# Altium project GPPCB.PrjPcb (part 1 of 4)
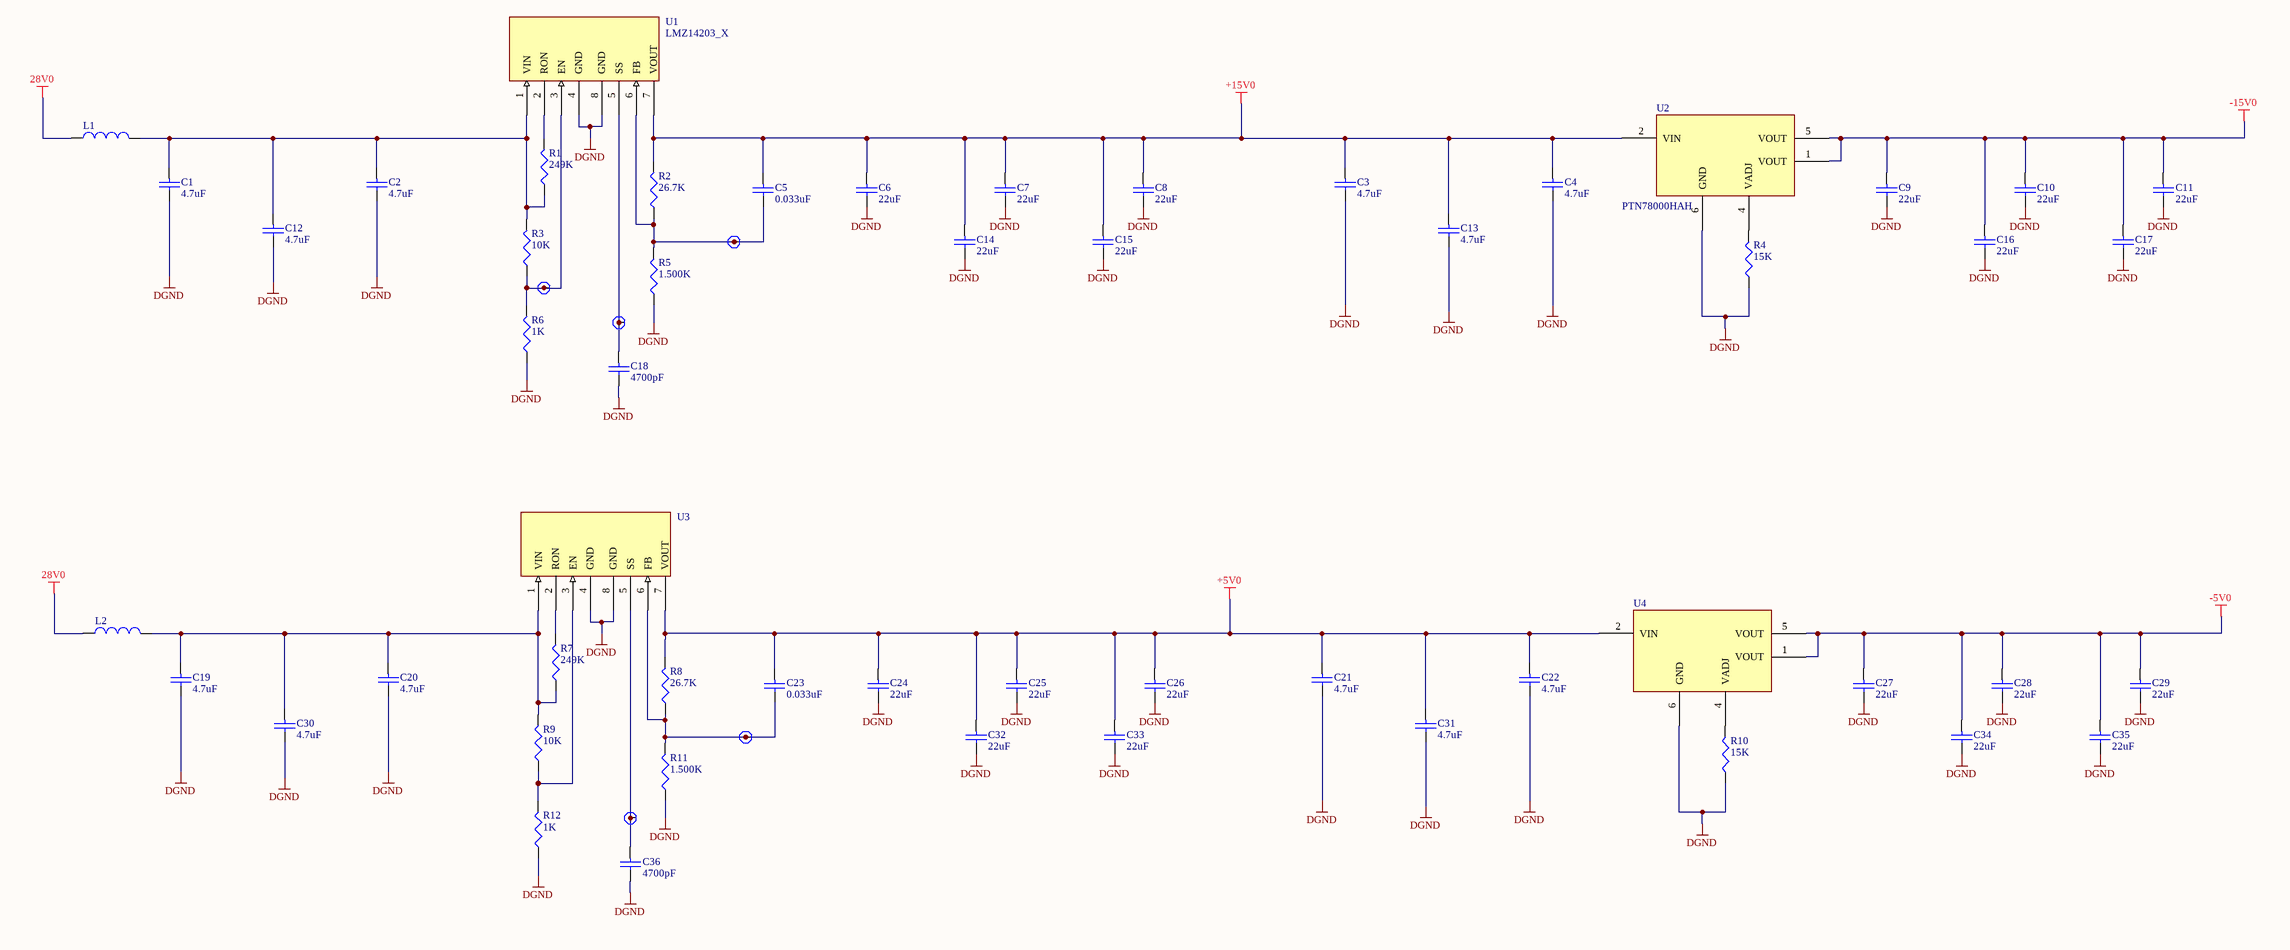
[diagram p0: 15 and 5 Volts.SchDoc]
15 sheets, 562 parts. Net scope: flat (ports and power ports of the same name join across sheets).
Board file: PCB2.PcbDoc
Sheets:
  15 and 5 Volts.SchDoc
  28 PowerSupply.SchDoc
  ByPass.SchDoc
  Connector.SchDoc
  Controller.SchDoc
  Decoder.SchDoc
  Latch1.SchDoc
  Latch2.SchDoc
  Latch3.SchDoc
  Latch4.SchDoc
  Latch5.SchDoc
  Latch6.SchDoc
  Latch7.SchDoc
  Protection.SchDoc
  Protection1.SchDoc

## Sheet 15 and 5 Volts.SchDoc: P.C. BOARD
size A2; Revision: A; SheetNumber: 2; SheetTotal: 19

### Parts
C1  value 4.7uF  [1210/2.8/N]  (hidden comment: 475-50V-10CX1210)
C2  value 4.7uF  [1210/2.8/N]  (hidden comment: 475-50V-10CX1210)
C3  value 4.7uF  [1210/2.8/N]  (hidden comment: 475-50V-10CX1210)
C4  value 4.7uF  [1210/2.8/N]  (hidden comment: 475-50V-10CX1210)
C5  value 0.033uF  [0805/1.3/N]  (hidden comment: 333-50V-10CX0805)
C6  value 22uF  [1210/2.8/N]  (hidden comment: 226-25V-10CX1210)
C7  value 22uF  [1210/2.8/N]  (hidden comment: 226-25V-10CX1210)
C8  value 22uF  [1210/2.8/N]  (hidden comment: 226-25V-10CX1210)
C9  value 22uF  [1210/2.8/N]  (hidden comment: 226-25V-10CX1210)
C10  value 22uF  [1210/2.8/N]  (hidden comment: 226-25V-10CX1210)
C11  value 22uF  [1210/2.8/N]  (hidden comment: 226-25V-10CX1210)
C12  value 4.7uF  [1210/2.8/N]  (hidden comment: 475-50V-10CX1210)
C13  value 4.7uF  [1210/2.8/N]  (hidden comment: 475-50V-10CX1210)
C14  value 22uF  [1210/2.8/N]  (hidden comment: 226-25V-10CX1210)
C15  value 22uF  [1210/2.8/N]  (hidden comment: 226-25V-10CX1210)
C16  value 22uF  [1210/2.8/N]  (hidden comment: 226-25V-10CX1210)
C17  value 22uF  [1210/2.8/N]  (hidden comment: 226-25V-10CX1210)
C18  value 4700pF  [0805/1.3/N]  (hidden comment: 472-101-10CX0805)
C19  value 4.7uF  [1210/2.8/N]  (hidden comment: 475-50V-10CX1210)
C20  value 4.7uF  [1210/2.8/N]  (hidden comment: 475-50V-10CX1210)
C21  value 4.7uF  [1210/2.8/N]  (hidden comment: 475-50V-10CX1210)
C22  value 4.7uF  [1210/2.8/N]  (hidden comment: 475-50V-10CX1210)
C23  value 0.033uF  [0805/1.3/N]  (hidden comment: 333-50V-10CX0805)
C24  value 22uF  [1210/2.8/N]  (hidden comment: 226-25V-10CX1210)
C25  value 22uF  [1210/2.8/N]  (hidden comment: 226-25V-10CX1210)
C26  value 22uF  [1210/2.8/N]  (hidden comment: 226-25V-10CX1210)
C27  value 22uF  [1210/2.8/N]  (hidden comment: 226-25V-10CX1210)
C28  value 22uF  [1210/2.8/N]  (hidden comment: 226-25V-10CX1210)
C29  value 22uF  [1210/2.8/N]  (hidden comment: 226-25V-10CX1210)
C30  value 4.7uF  [1210/2.8/N]  (hidden comment: 475-50V-10CX1210)
C31  value 4.7uF  [1210/2.8/N]  (hidden comment: 475-50V-10CX1210)
C32  value 22uF  [1210/2.8/N]  (hidden comment: 226-25V-10CX1210)
C33  value 22uF  [1210/2.8/N]  (hidden comment: 226-25V-10CX1210)
C34  value 22uF  [1210/2.8/N]  (hidden comment: 226-25V-10CX1210)
C35  value 22uF  [1210/2.8/N]  (hidden comment: 226-25V-10CX1210)
C36  value 4700pF  [0805/1.3/N]  (hidden comment: 472-101-10CX0805)
L1  2773019447_X  [SM-118/157]  (value not drawn)
L2  2773019447_X  [SM-118/157]  (value not drawn)
R1  value 249K  [0805/N]  (hidden comment: R249K0D1#0AX0805)
R2  value 26.7K  [0603/N]  (hidden comment: R26K70D1#0GX0603)
R3  value 10K  [0805/N]  (hidden comment: R10K00D1#0AX0805)
R4  value 15K  [0805/N]  (hidden comment: R15K00D1#0AX0805)
R5  value 1.500K  [0603/N]  (hidden comment: R1K500Z5#0AX0603)
R6  value 1K  [0805/N]  (hidden comment: R1K000D1#0AX0805)
R7  value 249K  [0805/N]  (hidden comment: R249K0D1#0AX0805)
R8  value 26.7K  [0603/N]  (hidden comment: R26K70D1#0GX0603)
R9  value 10K  [0805/N]  (hidden comment: R10K00D1#0AX0805)
R10  value 15K  [0805/N]  (hidden comment: R15K00D1#0AX0805)
R11  value 1.500K  [0603/N]  (hidden comment: R1K500Z5#0AX0603)
R12  value 1K  [0805/N]  (hidden comment: R1K000D1#0AX0805)
TP1  TP_SMT  [TP_SMT]  (value not drawn)
TP2  TP_SMT  [TP_SMT]  (value not drawn)
TP3  TP_SMT  [TP_SMT]  (value not drawn)
TP4  TP_SMT  [TP_SMT]  (value not drawn)
TP5  TP_SMT  [TP_SMT]  (value not drawn)
U1  LMZ14203_X  [TO-PMOD-7]
U2  PTN78000HAH  [R_PDSS_T5]
U3  LMZ14203_X  [TO-PMOD-7]  (value not drawn)
U4  PTN78000HAH  [R_PDSS_T5]  (value not drawn)

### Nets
28V0: L1.1 L2.1
+5V0: C21.1 C22.1 C23.1 C24.1 C25.1 C26.1 C31.1 C32.1 C33.1 R8.2 U3.7(VOUT) U4.2(VIN)
+15V0: C3.1 C4.1 C5.1 C6.1 C7.1 C8.1 C13.1 C14.1 C15.1 R2.2 U1.7(VOUT) U2.2(VIN)
-5V0: C27.1 C28.1 C29.1 C34.1 C35.1 U4.1(VOUT) U4.5(VOUT)
-15V0: C9.1 C10.1 C11.1 C16.1 C17.1 U2.1(VOUT) U2.5(VOUT)
DGND: C1.2 C2.2 C3.2 C4.2 C6.2 C7.2 C8.2 C9.2 C10.2 C11.2 C12.2 C13.2 C14.2 C15.2 C16.2 C17.2 C18.2 C19.2 C20.2 C21.2 C22.2 C24.2 C25.2 C26.2 C27.2 C28.2 C29.2 C30.2 C31.2 C32.2 C33.2 C34.2 C35.2 C36.2 R4.1 R5.1 R6.1 R10.1 R11.1 R12.1 U1.4(GND) U1.8(GND) U2.6(GND) U3.4(GND) U3.8(GND) U4.6(GND)
NetC1_1: C1.1 C2.1 C12.1 L1.2 R1.1 R3.2 U1.1(VIN)
NetC5_2: C5.2 R2.1 R5.2 TP1.1(TP) U1.6(FB)
NetC18_1: C18.1 TP3.1(TP) U1.5(SS)
NetC19_1: C19.1 C20.1 C30.1 L2.2 R7.1 R9.2 U3.1(VIN)
NetC23_2: C23.2 R8.1 R11.2 TP4.1(TP) U3.6(FB)
NetC36_1: C36.1 TP5.1(TP) U3.5(SS)
NetR1_2: R1.2 U1.2(RON)
NetR3_1: R3.1 R6.2 TP2.1(TP) U1.3(EN)
NetR4_2: R4.2 U2.4(VADJ)
NetR7_2: R7.2 U3.2(RON)
NetR9_1: R9.1 R12.2 U3.3(EN)
NetR10_2: R10.2 U4.4(VADJ)

Not connected (* = marked no-connect by the designer): U2 3(INH); U4 3(INH)

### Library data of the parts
C1-C4 C12 C13 C19-C22 C30 C31 = 475-50V-10CX1210: CAPACITOR, CERAMIC, 4.7UF 10%, X7R, 50V, 1210; AREA: 0.0174; TOLERANCE: 10; TYPE: CAP_X
C5 C23 = 333-50V-10CX0805: CAPACITOR, CERAMIC, 0.033UF 10%, X7R, 50V, 0805; AREA: 0.0066; TOLERANCE: 10; TYPE: CAP_X
C6-C11 C14-C17 C24-C29 C32-C35 = 226-25V-10CX1210: CAPACITOR, CERAMIC, 22UF 10%, X7R, 25V, 1210; AREA: 0.0174; TOLERANCE: 10; TYPE: CAP_X
C18 C36 = 472-101-10CX0805: CAPACITOR, CERAMIC, 4700PF 10%, X7R, 100V; AREA: 0.0066; TOLERANCE: 10; TYPE: CAP_X
L1 L2 = 2773019447_X: INDUCTOR, BEAD, SMT, < 50 MHz (73 material); AREA: 0.022; TYPE: CHOKE
R1 R7 = R249K0D1#0AX0805: RESISTOR, 249K OHMS, 1%, 0805; AMETEK PART NO: B1604-097; AREA: 0.0085; TOLERANCE: 1; DESIGNER: GRL 12/09/03
R2 R8 = R26K70D1#0GX0603: RESISTOR, 26.7K OHM, 1%, 100 PPM, 0603; AREA: 0.0055; TOLERANCE: 1
R3 R9 = R10K00D1#0AX0805: RESISTOR, 10K OHM, 1%, 100 PPM, 0805; AREA: 0.0085; TOLERANCE: 1
R4 R10 = R15K00D1#0AX0805: RESISTOR, 15K, 1%, 100 PPM, 0805; AREA: 0.0066; TOLERANCE: 1
R5 R11 = R1K500Z5#0AX0603: RESISTOR, 1.500K OHM, 5%, 200 PPM, 0603; AREA: 0.0055; TOLERANCE: 5
R6 R12 = R1K000D1#0AX0805: RESISTOR, 1K, 1%, 100 PPM, 0805; AREA: 0.0085; TOLERANCE: 1
TP1-TP5 = TP35: TEST POINT, 0.035 dia Oct pad w/ 0.010 hole, or SMT; AREA: 0.0012
U1 U3 = LMZ14203_X: 3A POWER MODULE, 42V MAX; AREA: 0.228
U2 U4 = PTN78000HAH: MODULE, 11.85V - 22V SWITCHING REGULATOR (1.5A); AREA: 0.42

## Sheet 28 PowerSupply.SchDoc: P.C. BOARD
size A2; Revision: A; SheetNumber: 1; SheetTotal: 19
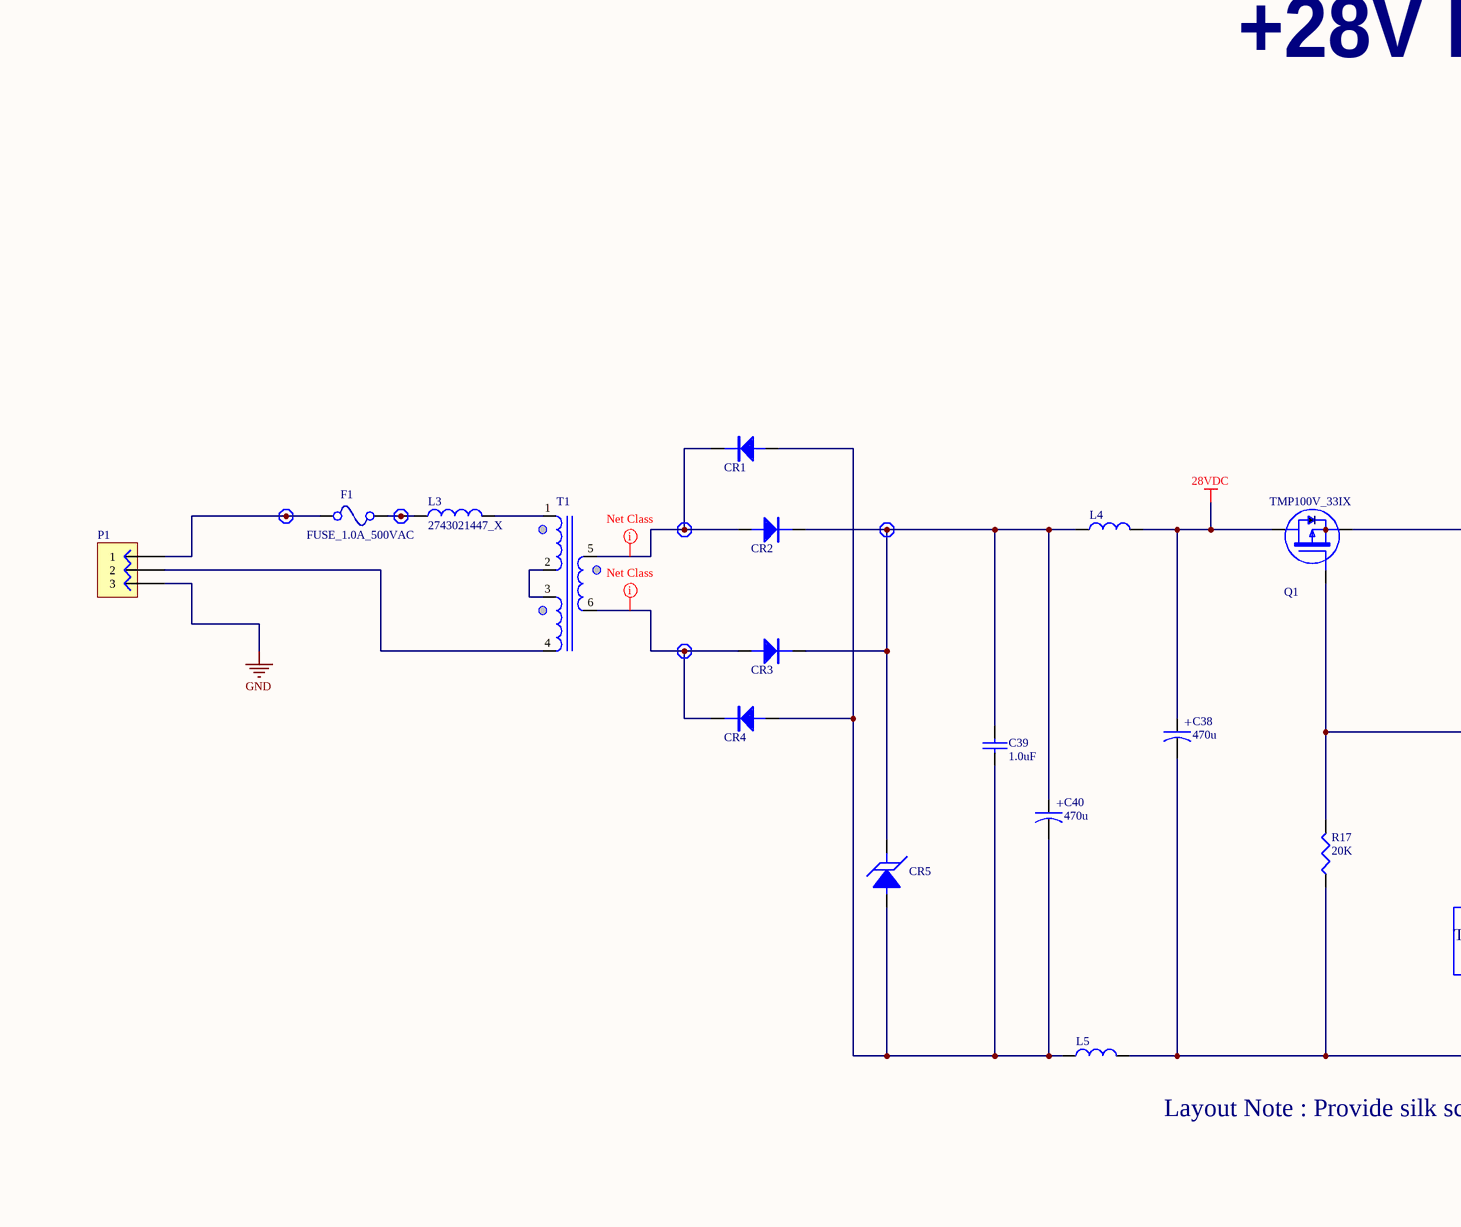
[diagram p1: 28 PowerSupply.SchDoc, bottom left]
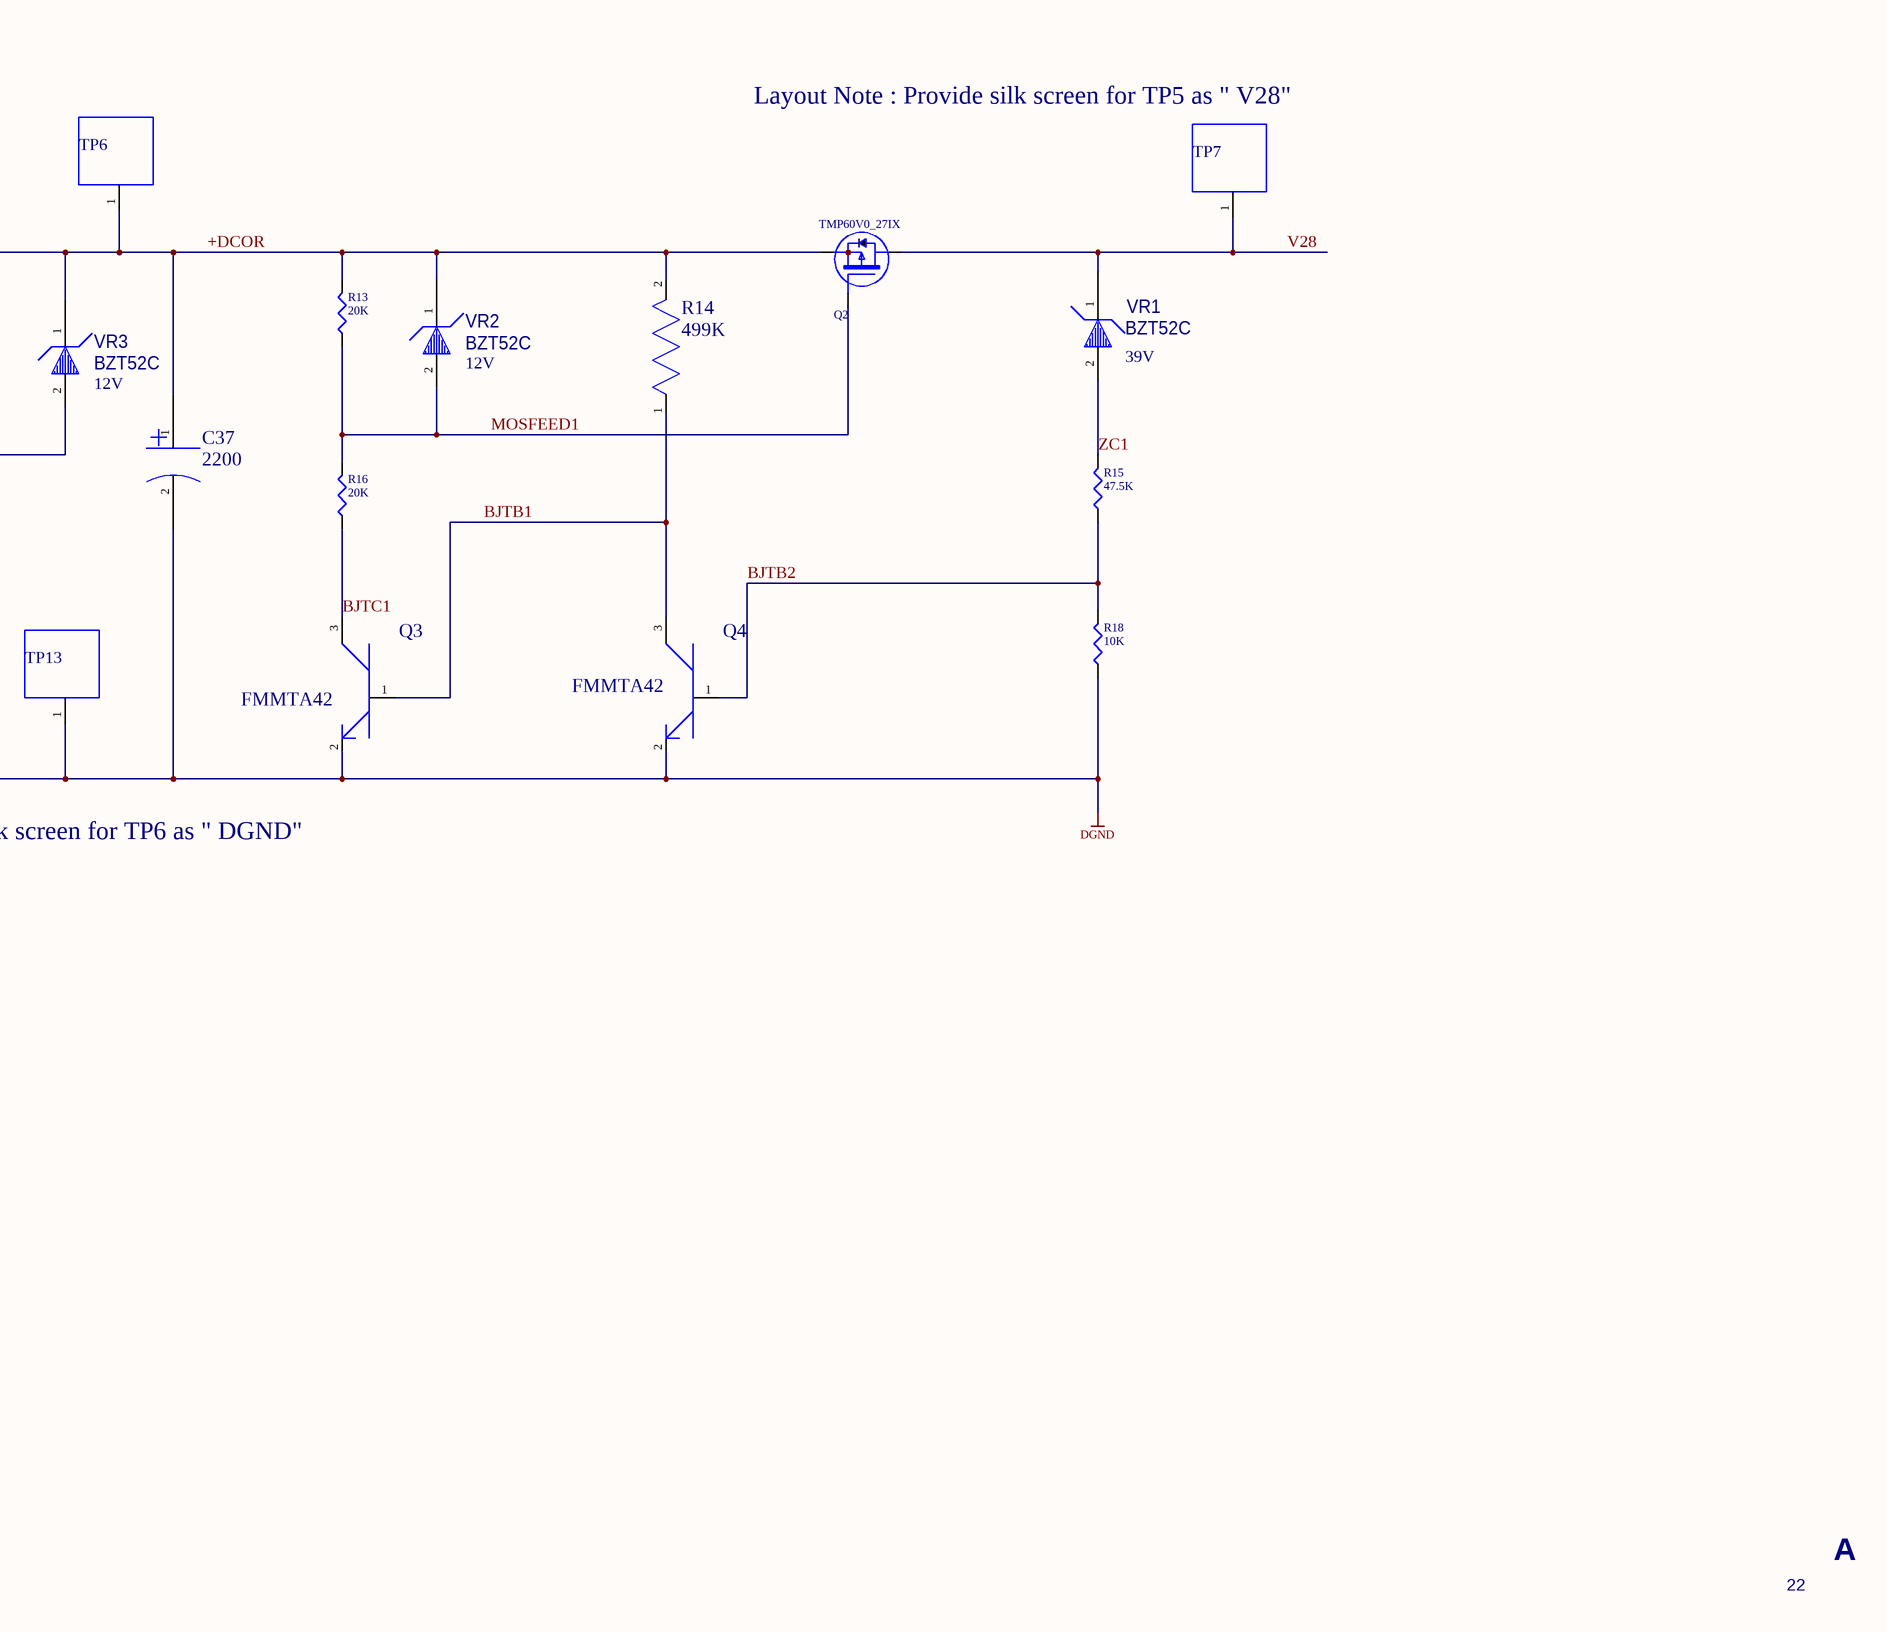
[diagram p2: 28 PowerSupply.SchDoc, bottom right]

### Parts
C37  value 2200  [CAP_MLP222M063EK0A]  (hidden comment: MLPCAPSHORT)
C38  value 470u  [RH+.2/.512/1]  (hidden comment: 477-50V-20AV)
C39  value 1.0uF  [1210/2.8/N]  (hidden comment: 105-101-10CX1210)
C40  value 470u  [RH+.2/.512/1]  (hidden comment: 477-50V-20AV)
CR1  D200V_2I0__X  [SMA/NP]  (value not drawn)
CR2  D200V_2I0__X  [SMA/NP]  (value not drawn)
CR3  D200V_2I0__X  [SMA/NP]  (value not drawn)
CR4  D200V_2I0__X  [SMA/NP]  (value not drawn)
CR5  Z36V0U3W0KZX  [DO-214AB+/NP]  (value not drawn)
F1  FUSE_1.0A_500VAC  [AX1.05/.228]
L3  2743021447_X  [SM-118/295]
L4  MSS1260  [IND_MSS1260]  (value not drawn)
L5  MSS1260  [IND_MSS1260]  (value not drawn)
P1  1X3 ST HDR 5  [H(JV01)]  (value not drawn)
Q1  TMP100V_33IX  [D2PAK4/N]
Q2  TMP60V0_27IX  [D2PAK4/N]
Q3  FMMTA42  [SOT-23/N]
Q4  FMMTA42  [SOT-23/N]
R13  value 20K  [1206/N]  (hidden comment: R20K00D1#0BX1206)
R14  value 499K  [1206/N]  (hidden comment: R1206_499K)
R15  value 47.5K  [1206/N]  (hidden comment: R47K50D1#0BX1206)
R16  value 20K  [1206/N]  (hidden comment: R20K00D1#0BX1206)
R17  value 20K  [1206/N]  (hidden comment: R20K00D1#0BX1206)
R18  value 10K  [1206/N]  (hidden comment: R10K00D1#0BX1206)
T1  (no value)
TP6  KEY5015  [KS5015_TP_X]  (value not drawn)
TP7  KEY5015  [KS5015_TP_X]  (value not drawn)
TP8  TP_30  [TP_30]  (value not drawn)
TP9  TP_30  [TP_30]  (value not drawn)
TP10  TP_30  [TP_30]  (value not drawn)
TP11  TP_30  [TP_30]  (value not drawn)
TP12  TP_30  [TP_30]  (value not drawn)
TP13  KEY5015  [KS5015_TP_X]  (value not drawn)
VR1  BZT52C  value 39V  [SOD323/NP]
VR2  BZT52C  value 12V  [SOD323]
VR3  BZT52C  value 12V  [SOD323]

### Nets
28VDC: C38.1 L4.2 Q1.4(D)
DGND: C37.2(N2) C38.2 L5.2 Q3.2(E) Q4.2(E) R17.1 R18.1 TP13.1(A)
GND: P1.3
+DCOR: C37.1(N1) Q1.3(S) Q2.3(S) R13.2 R14.2(N2) TP6.1(A) VR2.1(A) VR3.1(A)
BJTB1: Q3.1(B) Q4.3(C) R14.1(N1)
BJTB2: Q4.1(B) R15.1 R18.2
BJTC1: Q3.3(C) R16.1
MOSFEED1: Q2.1(G) R13.1 R16.2 VR2.2(K)
V28: Q2.4(D) TP7.1(A) VR1.1(N)
ZC1: R15.2 VR1.2(P)
NetC39_1: C39.1 C40.1 CR2.1(K) CR3.1(K) CR5.1(K) L4.1 TP11.1(TP)
NetC39_2: C39.2 C40.2 CR1.2(A) CR4.2(A) CR5.2(A) L5.1
NetCR1_1: CR1.1(K) CR2.2(A) T1.5 TP10.1(TP)
NetCR3_2: CR3.2(A) CR4.1(K) T1.6 TP12.1(TP)
NetF1_1: F1.1 P1.1 TP8.1(TP)
NetF1_2: F1.2 L3.1 TP9.1(TP)
NetL3_2: L3.2 T1.1
NetP1_2: P1.2 T1.4
NetQ1_1: Q1.1(G) R17.2 VR3.2(K)
NetT1_2: T1.2 T1.3

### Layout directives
net class Power1: NetCR1_1, NetCR3_2

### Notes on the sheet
- +28V POWER SUPPLY
- Layout Note : Provide silk screen for TP5 as " V28"
- Layout Note : Provide silk screen for TP6 as " DGND"
- 22
- A

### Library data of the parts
C37 = MLPCAPSHORT.1: VENDOR: CORNELL-DUBILIER; MFGRN: MLP222M063EK0A; LEVEL: STD; GEOMETRY.HEIGHT: 500.00MIL
C38 C40 = 477-50V-20AV: CAPACITOR, ALUM ELECT, 470UF, 50V, 477-50V-20AV, -55C TO 105 C; TYPE: CAP
C39 = 105-101-10CX1210: CAPACITOR, CERAMIC, 1.0UF 10%, X7R, 100V, 2.7mm; AREA: 0.0174; TOLERANCE: 10; TYPE: CAP_X
CR1-CR4 = D200V_2I0__X: DIODE, RECTIFIER, 200V, 2 AMP, SMA PACKAGE; AREA: 0.0302; TYPE: DIODE_X
CR5 = Z36V0U3W0KZX: DIODE, ZENER, 36V, DO214AB+; AREA: 0.088; TYPE: DIODE_X
F1 = FUSE_1A_A: FUSE, AXIAL LEADED, 1A, 500VAC; AMETEK PART NO: B1548-J-002; AREA: 0.228; TYPE: MISC; DESIGNER: CC
L3 = 2743021447_X: INDUCTOR, BEAD, SMT, 25-300MHz (43 material); AMETEK PART NO: B1489-AE-001; AREA: 0.06; TYPE: CHOKE; DESIGNER: 5/4/07   GTN
L4 L5 = 1489-BF33U_X: INDUCTOR, PWR, MSS1260; VENDOR: COILCRAFT; MFGRN: MSS1260-333MLD
P1 = 1X3 ST HDR 5: HEADER, 3 PIN, ST, 5mm CTRS; AREA: 0.475
Q1 = TMP100V_33IX: POWER MOSFET, P-CHANNEL, 100V, 33A, D2PAK; TYPE: TRANS_X
Q2 = TMP60V0_27IX: POWER MOSFET, P-CHANNEL, 60V, 27A, D2PAK; TYPE: TRANS_X
Q3 Q4 = FMMTA42.1: LEVEL: STD; VENDOR: ZETEX; MFGRN: FFMTA42; PKG_TYPE: SOT23; GEOMETRY.HEIGHT: 45.00MIL
R13 R16 R17 = R20K00D1#0BX1206: RESISTOR, 20K, 1%, 100 PPM, 1206; AREA: 0.0116; TOLERANCE: 1
R14 = R1206_499K: Resistor, General Purpose, 47.5K, 1%, 100 PPM, 1206; LEVEL: STD; PKG_TYPE: R1206; GEOMETRY.HEIGHT: 70.87MIL; VENDOR: PANASONIC; MFGRN: ERJ-8ENF4993V
R15 = R47K50D1#0BX1206: RESISTOR, THIN FILM 47.5K, 0.1%, 100 PPM, 1206; AREA: 0.0116; TOLERANCE: .1
R18 = R10K00D1#0BX1206: RESISTOR, 10K, 1%, 100 PPM, 1206; AREA: 0.0116; TOLERANCE: 1
T1 = B1460-BH-003: TRANSFORMER; TYPE: TRANSF
TP6 TP7 TP13 = KEY5015.1: VENDOR: KEYSTONE; MFGRN: 5015; LEVEL: STD; GEOMETRY.HEIGHT: 62.99MIL
TP8-TP12 = TP_SMT: AREA: 0.0012
VR1 = BZT52CXXX.1: PKG_TYPE: SOD-123; PREFIX: VR; GEOMETRY.HEIGHT: 1.35MIL; VENDOR: DIODES INC; MFGRN: BZT52C39
VR2 VR3 = BZT52C12S: PKG_TYPE: SOD-323; PREFIX: VR; GEOMETRY.HEIGHT: 1.35MIL; VENDOR: DIODES INC

## Sheet ByPass.SchDoc: P.C. BOARD
size A2; Revision: A; SheetNumber: 0; SheetTotal: 0
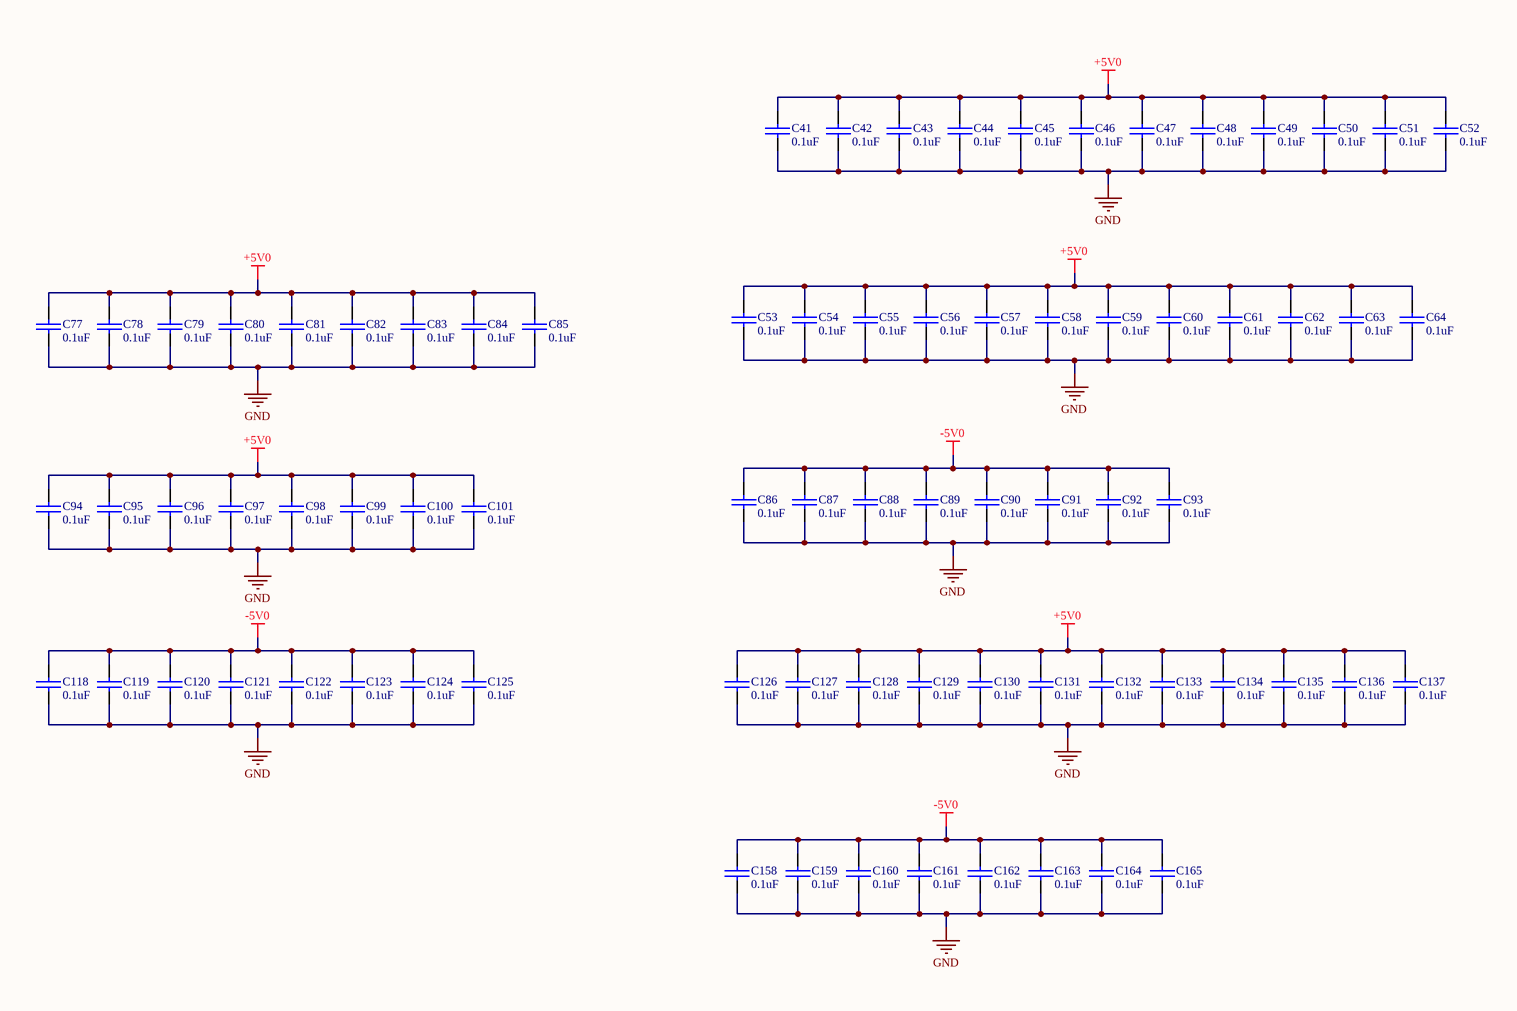
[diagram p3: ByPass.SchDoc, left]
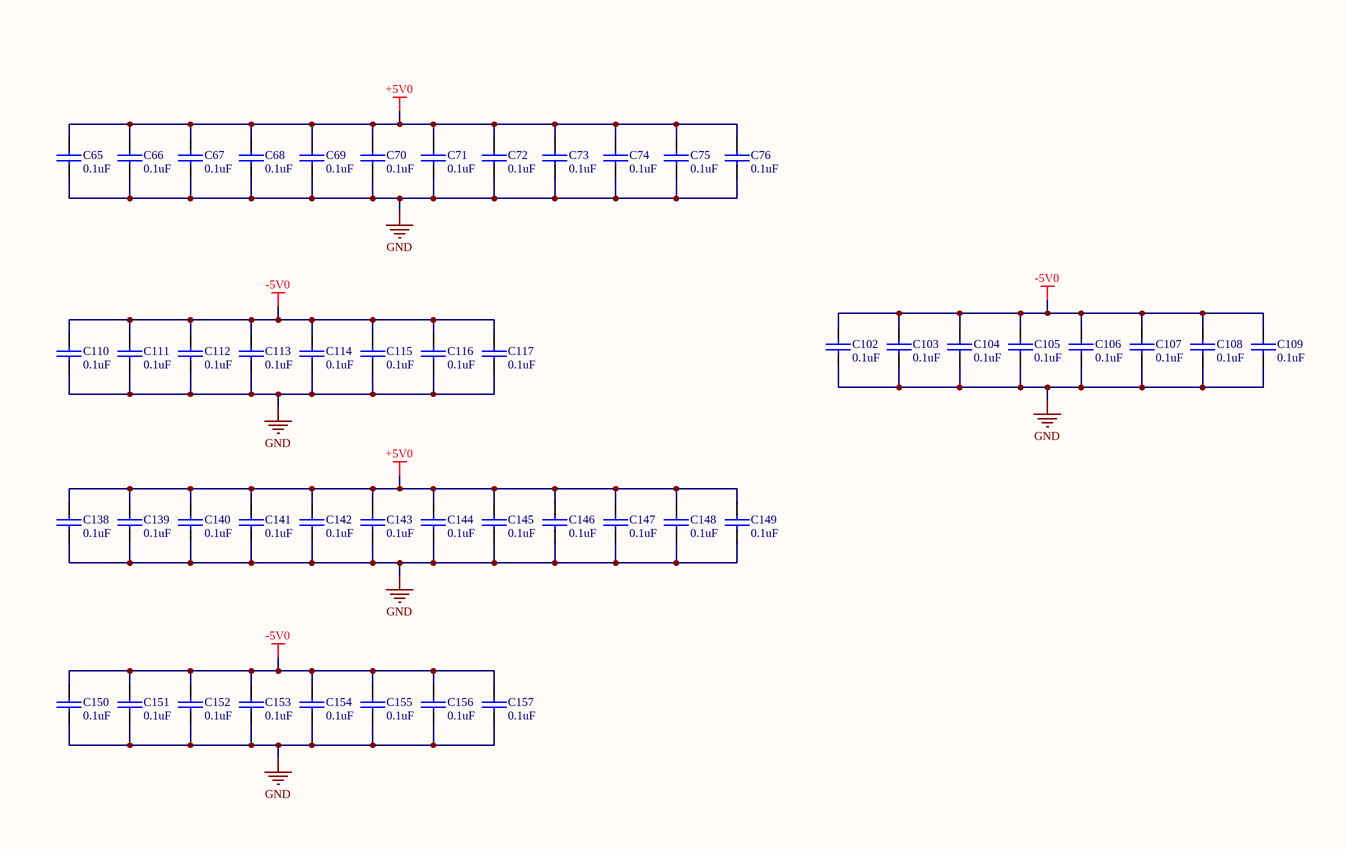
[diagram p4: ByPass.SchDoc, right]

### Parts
C41  value 0.1uF  [0805/1.3/N]  (hidden comment: 104-50V-10CX0805)
C42  value 0.1uF  [0805/1.3/N]  (hidden comment: 104-50V-10CX0805)
C43  value 0.1uF  [0805/1.3/N]  (hidden comment: 104-50V-10CX0805)
C44  value 0.1uF  [0805/1.3/N]  (hidden comment: 104-50V-10CX0805)
C45  value 0.1uF  [0805/1.3/N]  (hidden comment: 104-50V-10CX0805)
C46  value 0.1uF  [0805/1.3/N]  (hidden comment: 104-50V-10CX0805)
C47  value 0.1uF  [0805/1.3/N]  (hidden comment: 104-50V-10CX0805)
C48  value 0.1uF  [0805/1.3/N]  (hidden comment: 104-50V-10CX0805)
C49  value 0.1uF  [0805/1.3/N]  (hidden comment: 104-50V-10CX0805)
C50  value 0.1uF  [0805/1.3/N]  (hidden comment: 104-50V-10CX0805)
C51  value 0.1uF  [0805/1.3/N]  (hidden comment: 104-50V-10CX0805)
C52  value 0.1uF  [0805/1.3/N]  (hidden comment: 104-50V-10CX0805)
C53  value 0.1uF  [0805/1.3/N]  (hidden comment: 104-50V-10CX0805)
C54  value 0.1uF  [0805/1.3/N]  (hidden comment: 104-50V-10CX0805)
C55  value 0.1uF  [0805/1.3/N]  (hidden comment: 104-50V-10CX0805)
C56  value 0.1uF  [0805/1.3/N]  (hidden comment: 104-50V-10CX0805)
C57  value 0.1uF  [0805/1.3/N]  (hidden comment: 104-50V-10CX0805)
C58  value 0.1uF  [0805/1.3/N]  (hidden comment: 104-50V-10CX0805)
C59  value 0.1uF  [0805/1.3/N]  (hidden comment: 104-50V-10CX0805)
C60  value 0.1uF  [0805/1.3/N]  (hidden comment: 104-50V-10CX0805)
C61  value 0.1uF  [0805/1.3/N]  (hidden comment: 104-50V-10CX0805)
C62  value 0.1uF  [0805/1.3/N]  (hidden comment: 104-50V-10CX0805)
C63  value 0.1uF  [0805/1.3/N]  (hidden comment: 104-50V-10CX0805)
C64  value 0.1uF  [0805/1.3/N]  (hidden comment: 104-50V-10CX0805)
C65  value 0.1uF  [0805/1.3/N]  (hidden comment: 104-50V-10CX0805)
C66  value 0.1uF  [0805/1.3/N]  (hidden comment: 104-50V-10CX0805)
C67  value 0.1uF  [0805/1.3/N]  (hidden comment: 104-50V-10CX0805)
C68  value 0.1uF  [0805/1.3/N]  (hidden comment: 104-50V-10CX0805)
C69  value 0.1uF  [0805/1.3/N]  (hidden comment: 104-50V-10CX0805)
C70  value 0.1uF  [0805/1.3/N]  (hidden comment: 104-50V-10CX0805)
C71  value 0.1uF  [0805/1.3/N]  (hidden comment: 104-50V-10CX0805)
C72  value 0.1uF  [0805/1.3/N]  (hidden comment: 104-50V-10CX0805)
C73  value 0.1uF  [0805/1.3/N]  (hidden comment: 104-50V-10CX0805)
C74  value 0.1uF  [0805/1.3/N]  (hidden comment: 104-50V-10CX0805)
C75  value 0.1uF  [0805/1.3/N]  (hidden comment: 104-50V-10CX0805)
C76  value 0.1uF  [0805/1.3/N]  (hidden comment: 104-50V-10CX0805)
C77  value 0.1uF  [0805/1.3/N]  (hidden comment: 104-50V-10CX0805)
C78  value 0.1uF  [0805/1.3/N]  (hidden comment: 104-50V-10CX0805)
C79  value 0.1uF  [0805/1.3/N]  (hidden comment: 104-50V-10CX0805)
C80  value 0.1uF  [0805/1.3/N]  (hidden comment: 104-50V-10CX0805)
C81  value 0.1uF  [0805/1.3/N]  (hidden comment: 104-50V-10CX0805)
C82  value 0.1uF  [0805/1.3/N]  (hidden comment: 104-50V-10CX0805)
C83  value 0.1uF  [0805/1.3/N]  (hidden comment: 104-50V-10CX0805)
C84  value 0.1uF  [0805/1.3/N]  (hidden comment: 104-50V-10CX0805)
C85  value 0.1uF  [0805/1.3/N]  (hidden comment: 104-50V-10CX0805)
C86  value 0.1uF  [0805/1.3/N]  (hidden comment: 104-50V-10CX0805)
C87  value 0.1uF  [0805/1.3/N]  (hidden comment: 104-50V-10CX0805)
C88  value 0.1uF  [0805/1.3/N]  (hidden comment: 104-50V-10CX0805)
C89  value 0.1uF  [0805/1.3/N]  (hidden comment: 104-50V-10CX0805)
C90  value 0.1uF  [0805/1.3/N]  (hidden comment: 104-50V-10CX0805)
C91  value 0.1uF  [0805/1.3/N]  (hidden comment: 104-50V-10CX0805)
C92  value 0.1uF  [0805/1.3/N]  (hidden comment: 104-50V-10CX0805)
C93  value 0.1uF  [0805/1.3/N]  (hidden comment: 104-50V-10CX0805)
C94  value 0.1uF  [0805/1.3/N]  (hidden comment: 104-50V-10CX0805)
C95  value 0.1uF  [0805/1.3/N]  (hidden comment: 104-50V-10CX0805)
C96  value 0.1uF  [0805/1.3/N]  (hidden comment: 104-50V-10CX0805)
C97  value 0.1uF  [0805/1.3/N]  (hidden comment: 104-50V-10CX0805)
C98  value 0.1uF  [0805/1.3/N]  (hidden comment: 104-50V-10CX0805)
C99  value 0.1uF  [0805/1.3/N]  (hidden comment: 104-50V-10CX0805)
C100  value 0.1uF  [0805/1.3/N]  (hidden comment: 104-50V-10CX0805)
C101  value 0.1uF  [0805/1.3/N]  (hidden comment: 104-50V-10CX0805)
C102  value 0.1uF  [0805/1.3/N]  (hidden comment: 104-50V-10CX0805)
C103  value 0.1uF  [0805/1.3/N]  (hidden comment: 104-50V-10CX0805)
C104  value 0.1uF  [0805/1.3/N]  (hidden comment: 104-50V-10CX0805)
C105  value 0.1uF  [0805/1.3/N]  (hidden comment: 104-50V-10CX0805)
C106  value 0.1uF  [0805/1.3/N]  (hidden comment: 104-50V-10CX0805)
C107  value 0.1uF  [0805/1.3/N]  (hidden comment: 104-50V-10CX0805)
C108  value 0.1uF  [0805/1.3/N]  (hidden comment: 104-50V-10CX0805)
C109  value 0.1uF  [0805/1.3/N]  (hidden comment: 104-50V-10CX0805)
C110  value 0.1uF  [0805/1.3/N]  (hidden comment: 104-50V-10CX0805)
C111  value 0.1uF  [0805/1.3/N]  (hidden comment: 104-50V-10CX0805)
C112  value 0.1uF  [0805/1.3/N]  (hidden comment: 104-50V-10CX0805)
C113  value 0.1uF  [0805/1.3/N]  (hidden comment: 104-50V-10CX0805)
C114  value 0.1uF  [0805/1.3/N]  (hidden comment: 104-50V-10CX0805)
C115  value 0.1uF  [0805/1.3/N]  (hidden comment: 104-50V-10CX0805)
C116  value 0.1uF  [0805/1.3/N]  (hidden comment: 104-50V-10CX0805)
C117  value 0.1uF  [0805/1.3/N]  (hidden comment: 104-50V-10CX0805)
C118  value 0.1uF  [0805/1.3/N]  (hidden comment: 104-50V-10CX0805)
C119  value 0.1uF  [0805/1.3/N]  (hidden comment: 104-50V-10CX0805)
C120  value 0.1uF  [0805/1.3/N]  (hidden comment: 104-50V-10CX0805)
C121  value 0.1uF  [0805/1.3/N]  (hidden comment: 104-50V-10CX0805)
C122  value 0.1uF  [0805/1.3/N]  (hidden comment: 104-50V-10CX0805)
C123  value 0.1uF  [0805/1.3/N]  (hidden comment: 104-50V-10CX0805)
C124  value 0.1uF  [0805/1.3/N]  (hidden comment: 104-50V-10CX0805)
C125  value 0.1uF  [0805/1.3/N]  (hidden comment: 104-50V-10CX0805)
C126  value 0.1uF  [0805/1.3/N]  (hidden comment: 104-50V-10CX0805)
C127  value 0.1uF  [0805/1.3/N]  (hidden comment: 104-50V-10CX0805)
C128  value 0.1uF  [0805/1.3/N]  (hidden comment: 104-50V-10CX0805)
C129  value 0.1uF  [0805/1.3/N]  (hidden comment: 104-50V-10CX0805)
C130  value 0.1uF  [0805/1.3/N]  (hidden comment: 104-50V-10CX0805)
C131  value 0.1uF  [0805/1.3/N]  (hidden comment: 104-50V-10CX0805)
C132  value 0.1uF  [0805/1.3/N]  (hidden comment: 104-50V-10CX0805)
C133  value 0.1uF  [0805/1.3/N]  (hidden comment: 104-50V-10CX0805)
C134  value 0.1uF  [0805/1.3/N]  (hidden comment: 104-50V-10CX0805)
C135  value 0.1uF  [0805/1.3/N]  (hidden comment: 104-50V-10CX0805)
C136  value 0.1uF  [0805/1.3/N]  (hidden comment: 104-50V-10CX0805)
C137  value 0.1uF  [0805/1.3/N]  (hidden comment: 104-50V-10CX0805)
C138  value 0.1uF  [0805/1.3/N]  (hidden comment: 104-50V-10CX0805)
C139  value 0.1uF  [0805/1.3/N]  (hidden comment: 104-50V-10CX0805)
C140  value 0.1uF  [0805/1.3/N]  (hidden comment: 104-50V-10CX0805)
C141  value 0.1uF  [0805/1.3/N]  (hidden comment: 104-50V-10CX0805)
C142  value 0.1uF  [0805/1.3/N]  (hidden comment: 104-50V-10CX0805)
C143  value 0.1uF  [0805/1.3/N]  (hidden comment: 104-50V-10CX0805)
C144  value 0.1uF  [0805/1.3/N]  (hidden comment: 104-50V-10CX0805)
C145  value 0.1uF  [0805/1.3/N]  (hidden comment: 104-50V-10CX0805)
C146  value 0.1uF  [0805/1.3/N]  (hidden comment: 104-50V-10CX0805)
C147  value 0.1uF  [0805/1.3/N]  (hidden comment: 104-50V-10CX0805)
C148  value 0.1uF  [0805/1.3/N]  (hidden comment: 104-50V-10CX0805)
C149  value 0.1uF  [0805/1.3/N]  (hidden comment: 104-50V-10CX0805)
C150  value 0.1uF  [0805/1.3/N]  (hidden comment: 104-50V-10CX0805)
C151  value 0.1uF  [0805/1.3/N]  (hidden comment: 104-50V-10CX0805)
C152  value 0.1uF  [0805/1.3/N]  (hidden comment: 104-50V-10CX0805)
C153  value 0.1uF  [0805/1.3/N]  (hidden comment: 104-50V-10CX0805)
C154  value 0.1uF  [0805/1.3/N]  (hidden comment: 104-50V-10CX0805)
C155  value 0.1uF  [0805/1.3/N]  (hidden comment: 104-50V-10CX0805)
C156  value 0.1uF  [0805/1.3/N]  (hidden comment: 104-50V-10CX0805)
C157  value 0.1uF  [0805/1.3/N]  (hidden comment: 104-50V-10CX0805)
C158  value 0.1uF  [0805/1.3/N]  (hidden comment: 104-50V-10CX0805)
C159  value 0.1uF  [0805/1.3/N]  (hidden comment: 104-50V-10CX0805)
C160  value 0.1uF  [0805/1.3/N]  (hidden comment: 104-50V-10CX0805)
C161  value 0.1uF  [0805/1.3/N]  (hidden comment: 104-50V-10CX0805)
C162  value 0.1uF  [0805/1.3/N]  (hidden comment: 104-50V-10CX0805)
C163  value 0.1uF  [0805/1.3/N]  (hidden comment: 104-50V-10CX0805)
C164  value 0.1uF  [0805/1.3/N]  (hidden comment: 104-50V-10CX0805)
C165  value 0.1uF  [0805/1.3/N]  (hidden comment: 104-50V-10CX0805)

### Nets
+5V0: C41.1 C42.1 C43.1 C44.1 C45.1 C46.1 C47.1 C48.1 C49.1 C50.1 C51.1 C52.1 C53.1 C54.1 C55.1 C56.1 C57.1 C58.1 C59.1 C60.1 C61.1 C62.1 C63.1 C64.1 C65.1 C66.1 C67.1 C68.1 C69.1 C70.1 C71.1 C72.1 C73.1 C74.1 C75.1 C76.1 C77.1 C78.1 C79.1 C80.1 C81.1 C82.1 C83.1 C84.1 C85.1 C94.1 C95.1 C96.1 C97.1 C98.1 C99.1 C100.1 C101.1 C126.1 C127.1 C128.1 C129.1 C130.1 C131.1 C132.1 C133.1 C134.1 C135.1 C136.1 C137.1 C138.1 C139.1 C140.1 C141.1 C142.1 C143.1 C144.1 C145.1 C146.1 C147.1 C148.1 C149.1
-5V0: C86.1 C87.1 C88.1 C89.1 C90.1 C91.1 C92.1 C93.1 C102.1 C103.1 C104.1 C105.1 C106.1 C107.1 C108.1 C109.1 C110.1 C111.1 C112.1 C113.1 C114.1 C115.1 C116.1 C117.1 C118.1 C119.1 C120.1 C121.1 C122.1 C123.1 C124.1 C125.1 C150.1 C151.1 C152.1 C153.1 C154.1 C155.1 C156.1 C157.1 C158.1 C159.1 C160.1 C161.1 C162.1 C163.1 C164.1 C165.1
GND: C41.2 C42.2 C43.2 C44.2 C45.2 C46.2 C47.2 C48.2 C49.2 C50.2 C51.2 C52.2 C53.2 C54.2 C55.2 C56.2 C57.2 C58.2 C59.2 C60.2 C61.2 C62.2 C63.2 C64.2 C65.2 C66.2 C67.2 C68.2 C69.2 C70.2 C71.2 C72.2 C73.2 C74.2 C75.2 C76.2 C77.2 C78.2 C79.2 C80.2 C81.2 C82.2 C83.2 C84.2 C85.2 C86.2 C87.2 C88.2 C89.2 C90.2 C91.2 C92.2 C93.2 C94.2 C95.2 C96.2 C97.2 C98.2 C99.2 C100.2 C101.2 C102.2 C103.2 C104.2 C105.2 C106.2 C107.2 C108.2 C109.2 C110.2 C111.2 C112.2 C113.2 C114.2 C115.2 C116.2 C117.2 C118.2 C119.2 C120.2 C121.2 C122.2 C123.2 C124.2 C125.2 C126.2 C127.2 C128.2 C129.2 C130.2 C131.2 C132.2 C133.2 C134.2 C135.2 C136.2 C137.2 C138.2 C139.2 C140.2 C141.2 C142.2 C143.2 C144.2 C145.2 C146.2 C147.2 C148.2 C149.2 C150.2 C151.2 C152.2 C153.2 C154.2 C155.2 C156.2 C157.2 C158.2 C159.2 C160.2 C161.2 C162.2 C163.2 C164.2 C165.2

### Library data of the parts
C41-C165 = 104-50V-10CX0805: CAPACITOR, CERAMIC, 0.1UF, 10%, X7R, 50V, 0805; AMETEK PART NO: B1605-029; AREA: 0.0066; TOLERANCE: 10; TYPE: CAP_X; CHECKER: GRL 5/20/02; DESIGNER: GTN 3/15/03

## Sheet Connector.SchDoc: P.C. BOARD
size A2; Revision: A; SheetNumber: 0; SheetTotal: 0
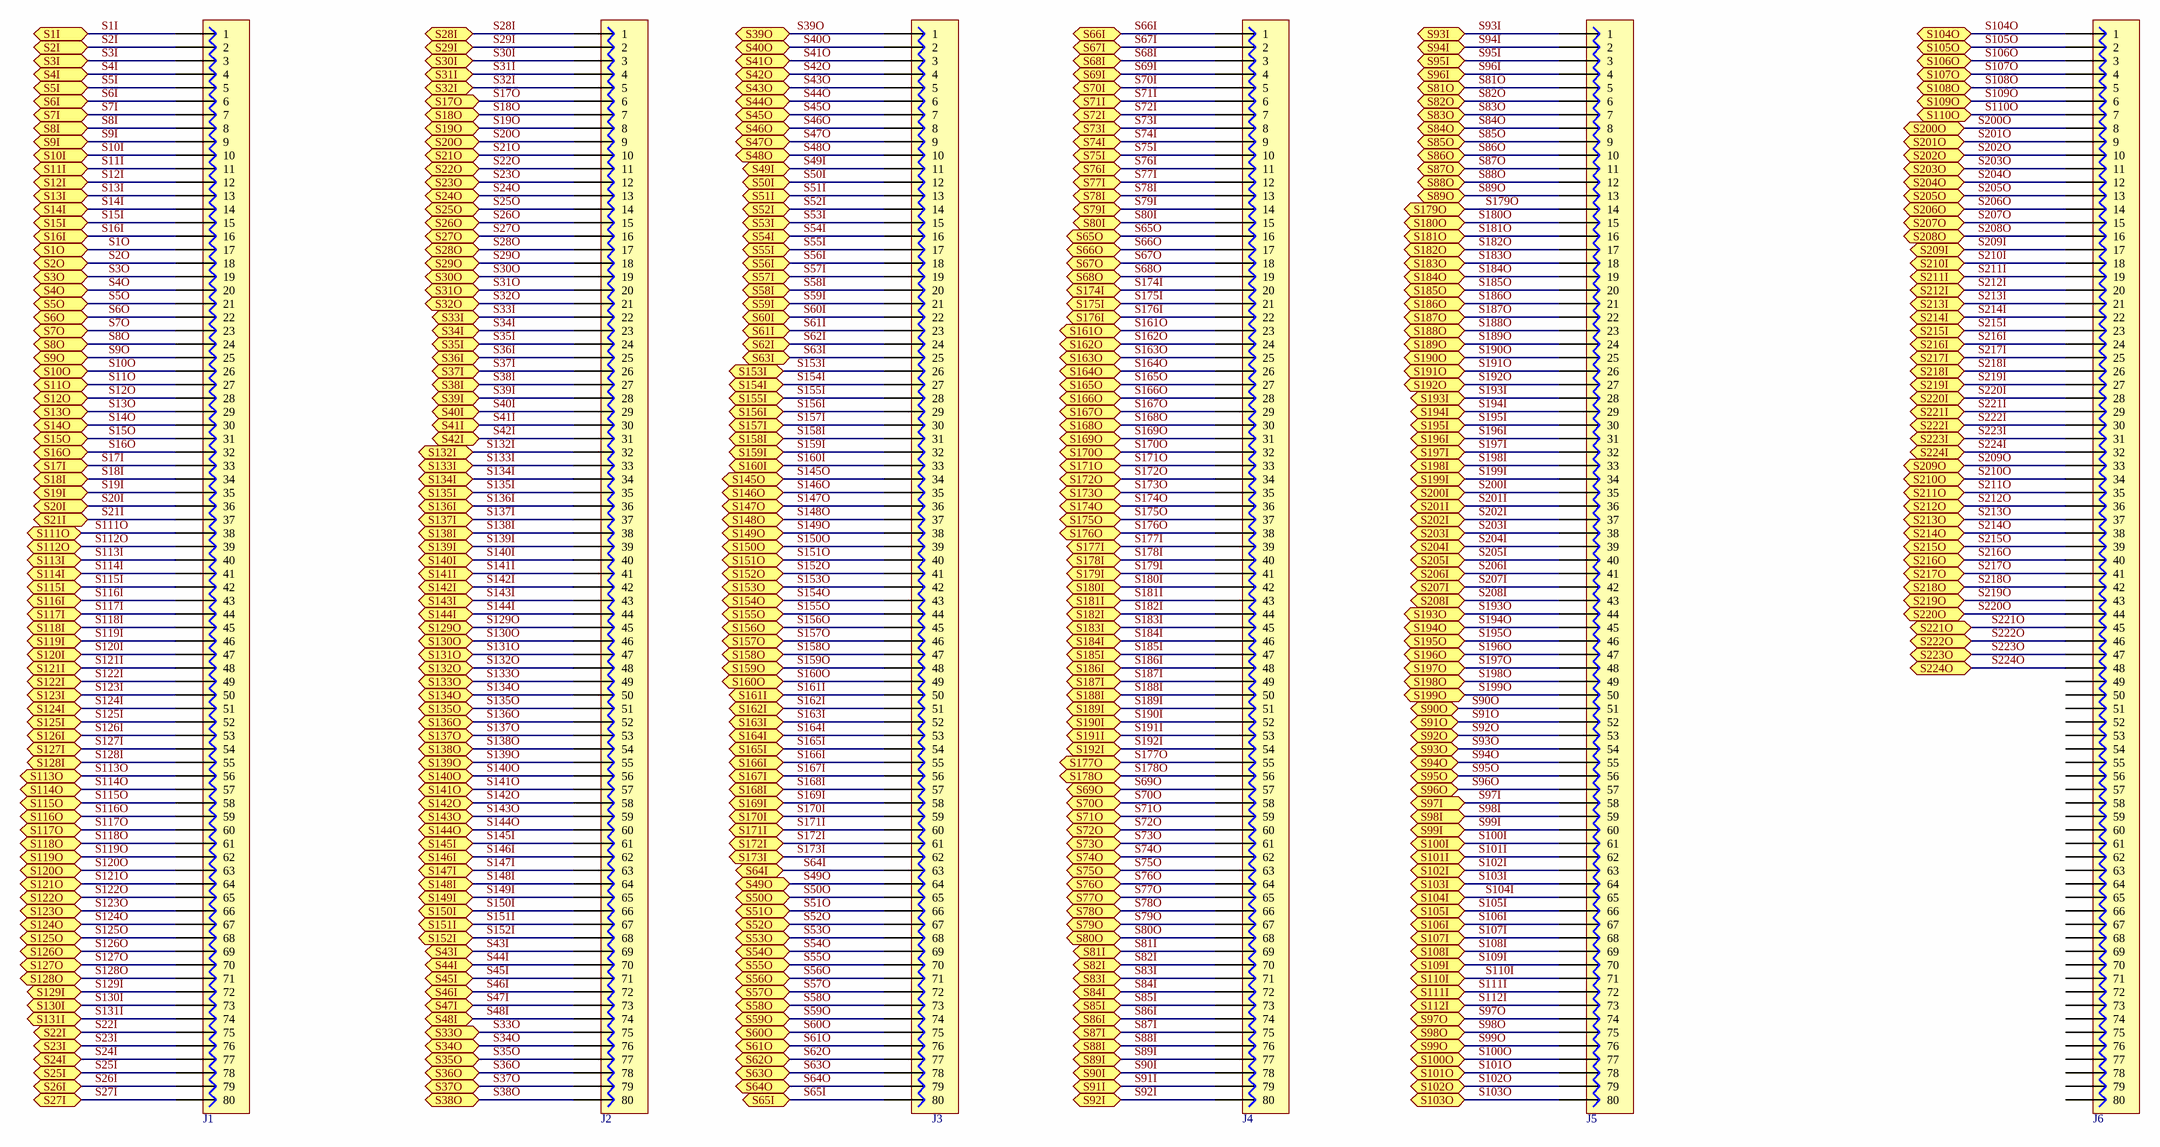
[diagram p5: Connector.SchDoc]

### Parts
J1  2X40 HDR  [H2X40]  (value not drawn)
J2  2X40 HDR  [H2X40]  (value not drawn)
J3  2X40 HDR  [H2X40]  (value not drawn)
J4  2X40 HDR  [H2X40]  (value not drawn)
J5  2X40 HDR  [H2X40]  (value not drawn)
J6  2X40 HDR  [H2X40]  (value not drawn)

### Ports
S1I (bidir), S1O (bidir), S2I (bidir), S2O (bidir), S3I (bidir), S3O (bidir), S4I (bidir), S4O (bidir), S5I (bidir), S5O (bidir), S6I (bidir), S6O (bidir), S7I (bidir), S7O (bidir), S8I (bidir), S8O (bidir), S9I (bidir), S9O (bidir), S10I (bidir), S10O (bidir), S11I (bidir), S11O (bidir), S12I (bidir), S12O (bidir), S13I (bidir), S13O (bidir), S14I (bidir), S14O (bidir), S15I (bidir), S15O (bidir), S16I (bidir), S16O (bidir), S17I (bidir), S17O (bidir), S18I (bidir), S18O (bidir), S19I (bidir), S19O (bidir), S20I (bidir), S20O (bidir), S21I (bidir), S21O (bidir), S22I (bidir), S22O (bidir), S23I (bidir), S23O (bidir), S24I (bidir), S24O (bidir), S25I (bidir), S25O (bidir), S26I (bidir), S26O (bidir), S27I (bidir), S27O (bidir), S28I (bidir), S28O (bidir), S29I (bidir), S29O (bidir), S30I (bidir), S30O (bidir), S31I (bidir), S31O (bidir), S32I (bidir), S32O (bidir), S33I (bidir), S33O (bidir), S34I (bidir), S34O (bidir), S35I (bidir), S35O (bidir), S36I (bidir), S36O (bidir), S37I (bidir), S37O (bidir), S38I (bidir), S38O (bidir), S39I (bidir), S39O (bidir), S40I (bidir), S40O (bidir), S41I (bidir), S41O (bidir), S42I (bidir), S42O (bidir), S43I (bidir), S43O (bidir), S44I (bidir), S44O (bidir), S45I (bidir), S45O (bidir), S46I (bidir), S46O (bidir), S47I (bidir), S47O (bidir), S48I (bidir), S48O (bidir), S49I (bidir), S49O (bidir), S50I (bidir), S50O (bidir), S51I (bidir), S51O (bidir), S52I (bidir), S52O (bidir), S53I (bidir), S53O (bidir), S54I (bidir), S54O (bidir), S55I (bidir), S55O (bidir), S56I (bidir), S56O (bidir), S57I (bidir), S57O (bidir), S58I (bidir), S58O (bidir), S59I (bidir), S59O (bidir), S60I (bidir), S60O (bidir), S61I (bidir), S61O (bidir), S62I (bidir), S62O (bidir), S63I (bidir), S63O (bidir), S64I (bidir), S64O (bidir), S65I (bidir), S65O (bidir), S66I (bidir), S66O (bidir), S67I (bidir), S67O (bidir), S68I (bidir), S68O (bidir), S69I (bidir), S69O (bidir), S70I (bidir), S70O (bidir), S71I (bidir), S71O (bidir), S72I (bidir), S72O (bidir), S73I (bidir), S73O (bidir), S74I (bidir), S74O (bidir), S75I (bidir), S75O (bidir), S76I (bidir), S76O (bidir), S77I (bidir), S77O (bidir), S78I (bidir), S78O (bidir), S79I (bidir), S79O (bidir), S80I (bidir), S80O (bidir), S81I (bidir), S81O (bidir), S82I (bidir), S82O (bidir), S83I (bidir), S83O (bidir), S84I (bidir), S84O (bidir), S85I (bidir), S85O (bidir), S86I (bidir), S86O (bidir), S87I (bidir), S87O (bidir), S88I (bidir), S88O (bidir), S89I (bidir), S89O (bidir), S90I (bidir), S90O (bidir), S91I (bidir), S91O (bidir), S92I (bidir), S92O (bidir), S93I (bidir), S93O (bidir), S94I (bidir), S94O (bidir), S95I (bidir), S95O (bidir), S96I (bidir), S96O (bidir), S97I (bidir), S97O (bidir), S98I (bidir), S98O (bidir), S99I (bidir), S99O (bidir), S100I (bidir), S100O (bidir), S101I (bidir), S101O (bidir), S102I (bidir), S102O (bidir), S103I (bidir), S103O (bidir), S104I (bidir), S104O (bidir), S105I (bidir), S105O (bidir), S106I (bidir), S106O (bidir), S107I (bidir), S107O (bidir), S108I (bidir), S108O (bidir), S109I (bidir), S109O (bidir), S110I (bidir), S110O (bidir), S111I (bidir), S111O (bidir), S112I (bidir), S112O (bidir), S113I (bidir), S113O (bidir), S114I (bidir), S114O (bidir), S115I (bidir), S115O (bidir), S116I (bidir), S116O (bidir), S117I (bidir), S117O (bidir), S118I (bidir), S118O (bidir), S119I (bidir), S119O (bidir), S120I (bidir), S120O (bidir), S121I (bidir), S121O (bidir), S122I (bidir), S122O (bidir), S123I (bidir), S123O (bidir), S124I (bidir), S124O (bidir), S125I (bidir), S125O (bidir), S126I (bidir), S126O (bidir), S127I (bidir), S127O (bidir), S128I (bidir), S128O (bidir), S129I (bidir), S129O (bidir), S130I (bidir), S130O (bidir), S131I (bidir), S131O (bidir), S132I (bidir), S132O (bidir), S133I (bidir), S133O (bidir), S134I (bidir), S134O (bidir), S135I (bidir), S135O (bidir), S136I (bidir), S136O (bidir), S137I (bidir), S137O (bidir), S138I (bidir), S138O (bidir), S139I (bidir), S139O (bidir), S140I (bidir), S140O (bidir), S141I (bidir), S141O (bidir), S142I (bidir), S142O (bidir), S143I (bidir), S143O (bidir), S144I (bidir), S144O (bidir), S145I (bidir), S145O (bidir), S146I (bidir), S146O (bidir), S147I (bidir), S147O (bidir), S148I (bidir), S148O (bidir), S149I (bidir), S149O (bidir), S150I (bidir), S150O (bidir), S151I (bidir), S151O (bidir), S152I (bidir), S152O (bidir), S153I (bidir), S153O (bidir), S154I (bidir), S154O (bidir), S155I (bidir), S155O (bidir), S156I (bidir), S156O (bidir), S157I (bidir), S157O (bidir), S158I (bidir), S158O (bidir), S159I (bidir), S159O (bidir), S160I (bidir), S160O (bidir), S161I (bidir), S161O (bidir), S162I (bidir), S162O (bidir), S163I (bidir), S163O (bidir), S164I (bidir), S164O (bidir), S165I (bidir), S165O (bidir), S166I (bidir), S166O (bidir), S167I (bidir), S167O (bidir), S168I (bidir), S168O (bidir), S169I (bidir), S169O (bidir), S170I (bidir), S170O (bidir), S171I (bidir), S171O (bidir), S172I (bidir), S172O (bidir), S173I (bidir), S173O (bidir), S174I (bidir), S174O (bidir), S175I (bidir), S175O (bidir), S176I (bidir), S176O (bidir), S177I (bidir), S177O (bidir), S178I (bidir), S178O (bidir), S179I (bidir), S179O (bidir), S180I (bidir), S180O (bidir), S181I (bidir), S181O (bidir), S182I (bidir), S182O (bidir), S183I (bidir), S183O (bidir), S184I (bidir), S184O (bidir), S185I (bidir), S185O (bidir), S186I (bidir), S186O (bidir), S187I (bidir), S187O (bidir), S188I (bidir), S188O (bidir), S189I (bidir), S189O (bidir), S190I (bidir), S190O (bidir), S191I (bidir), S191O (bidir), S192I (bidir), S192O (bidir), S193I (bidir), S193O (bidir), S194I (bidir), S194O (bidir), S195I (bidir), S195O (bidir), S196I (bidir), S196O (bidir), S197I (bidir), S197O (bidir), S198I (bidir), S198O (bidir), S199I (bidir), S199O (bidir), S200I (bidir), S200O (bidir), S201I (bidir), S201O (bidir), S202I (bidir), S202O (bidir), S203I (bidir), S203O (bidir), S204I (bidir), S204O (bidir), S205I (bidir), S205O (bidir), S206I (bidir), S206O (bidir), S207I (bidir), S207O (bidir), S208I (bidir), S208O (bidir), S209I (bidir), S209O (bidir), S210I (bidir), S210O (bidir), S211I (bidir), S211O (bidir), S212I (bidir), S212O (bidir), S213I (bidir), S213O (bidir), S214I (bidir), S214O (bidir), S215I (bidir), S215O (bidir), S216I (bidir), S216O (bidir), S217I (bidir), S217O (bidir), S218I (bidir), S218O (bidir), S219I (bidir), S219O (bidir), S220I (bidir), S220O (bidir), S221I (bidir), S221O (bidir), S222I (bidir), S222O (bidir), S223I (bidir), S223O (bidir), S224I (bidir), S224O (bidir)

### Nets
S1I: J1.1 ; port S1I
S1O: J1.17 ; port S1O
S2I: J1.2 ; port S2I
S2O: J1.18 ; port S2O
S3I: J1.3 ; port S3I
S3O: J1.19 ; port S3O
S4I: J1.4 ; port S4I
S4O: J1.20 ; port S4O
S5I: J1.5 ; port S5I
S5O: J1.21 ; port S5O
S6I: J1.6 ; port S6I
S6O: J1.22 ; port S6O
S7I: J1.7 ; port S7I
S7O: J1.23 ; port S7O
S8I: J1.8 ; port S8I
S8O: J1.24 ; port S8O
S9I: J1.9 ; port S9I
S9O: J1.25 ; port S9O
S10I: J1.10 ; port S10I
S10O: J1.26 ; port S10O
S11I: J1.11 ; port S11I
S11O: J1.27 ; port S11O
S12I: J1.12 ; port S12I
S12O: J1.28 ; port S12O
S13I: J1.13 ; port S13I
S13O: J1.29 ; port S13O
S14I: J1.14 ; port S14I
S14O: J1.30 ; port S14O
S15I: J1.15 ; port S15I
S15O: J1.31 ; port S15O
S16I: J1.16 ; port S16I
S16O: J1.32 ; port S16O
S17I: J1.33 ; port S17I
S17O: J2.6 ; port S17O
S18I: J1.34 ; port S18I
S18O: J2.7 ; port S18O
S19I: J1.35 ; port S19I
S19O: J2.8 ; port S19O
S20I: J1.36 ; port S20I
S20O: J2.9 ; port S20O
S21I: J1.37 ; port S21I
S21O: J2.10 ; port S21O
S22I: J1.75 ; port S22I
S22O: J2.11 ; port S22O
S23I: J1.76 ; port S23I
S23O: J2.12 ; port S23O
S24I: J1.77 ; port S24I
S24O: J2.13 ; port S24O
S25I: J1.78 ; port S25I
S25O: J2.14 ; port S25O
S26I: J1.79 ; port S26I
S26O: J2.15 ; port S26O
S27I: J1.80 ; port S27I
S27O: J2.16 ; port S27O
S28I: J2.1 ; port S28I
S28O: J2.17 ; port S28O
S29I: J2.2 ; port S29I
S29O: J2.18 ; port S29O
S30I: J2.3 ; port S30I
S30O: J2.19 ; port S30O
S31I: J2.4 ; port S31I
S31O: J2.20 ; port S31O
S32I: J2.5 ; port S32I
S32O: J2.21 ; port S32O
S33I: J2.22 ; port S33I
S33O: J2.75 ; port S33O
S34I: J2.23 ; port S34I
S34O: J2.76 ; port S34O
S35I: J2.24 ; port S35I
S35O: J2.77 ; port S35O
S36I: J2.25 ; port S36I
S36O: J2.78 ; port S36O
S37I: J2.26 ; port S37I
S37O: J2.79 ; port S37O
S38I: J2.27 ; port S38I
S38O: J2.80 ; port S38O
S39I: J2.28 ; port S39I
S39O: J3.1 ; port S39O
S40I: J2.29 ; port S40I
S40O: J3.2 ; port S40O
S41I: J2.30 ; port S41I
S41O: J3.3 ; port S41O
S42I: J2.31 ; port S42I
S42O: J3.4 ; port S42O
S43I: J2.69 ; port S43I
S43O: J3.5 ; port S43O
S44I: J2.70 ; port S44I
S44O: J3.6 ; port S44O
S45I: J2.71 ; port S45I
S45O: J3.7 ; port S45O
S46I: J2.72 ; port S46I
S46O: J3.8 ; port S46O
S47I: J2.73 ; port S47I
S47O: J3.9 ; port S47O
S48I: J2.74 ; port S48I
S48O: J3.10 ; port S48O
S49I: J3.11 ; port S49I
S49O: J3.64 ; port S49O
S50I: J3.12 ; port S50I
S50O: J3.65 ; port S50O
S51I: J3.13 ; port S51I
S51O: J3.66 ; port S51O
S52I: J3.14 ; port S52I
S52O: J3.67 ; port S52O
S53I: J3.15 ; port S53I
S53O: J3.68 ; port S53O
S54I: J3.16 ; port S54I
S54O: J3.69 ; port S54O
S55I: J3.17 ; port S55I
S55O: J3.70 ; port S55O
S56I: J3.18 ; port S56I
S56O: J3.71 ; port S56O
S57I: J3.19 ; port S57I
S57O: J3.72 ; port S57O
S58I: J3.20 ; port S58I
S58O: J3.73 ; port S58O
S59I: J3.21 ; port S59I
S59O: J3.74 ; port S59O
S60I: J3.22 ; port S60I
S60O: J3.75 ; port S60O
S61I: J3.23 ; port S61I
S61O: J3.76 ; port S61O
S62I: J3.24 ; port S62I
S62O: J3.77 ; port S62O
S63I: J3.25 ; port S63I
S63O: J3.78 ; port S63O
S64I: J3.63 ; port S64I
S64O: J3.79 ; port S64O
S65I: J3.80 ; port S65I
S65O: J4.16 ; port S65O
S66I: J4.1 ; port S66I
S66O: J4.17 ; port S66O
S67I: J4.2 ; port S67I
S67O: J4.18 ; port S67O
S68I: J4.3 ; port S68I
S68O: J4.19 ; port S68O
S69I: J4.4 ; port S69I
S69O: J4.57 ; port S69O
S70I: J4.5 ; port S70I
S70O: J4.58 ; port S70O
S71I: J4.6 ; port S71I
S71O: J4.59 ; port S71O
S72I: J4.7 ; port S72I
S72O: J4.60 ; port S72O
S73I: J4.8 ; port S73I
S73O: J4.61 ; port S73O
S74I: J4.9 ; port S74I
S74O: J4.62 ; port S74O
S75I: J4.10 ; port S75I
S75O: J4.63 ; port S75O
S76I: J4.11 ; port S76I
S76O: J4.64 ; port S76O
S77I: J4.12 ; port S77I
S77O: J4.65 ; port S77O
S78I: J4.13 ; port S78I
S78O: J4.66 ; port S78O
S79I: J4.14 ; port S79I
S79O: J4.67 ; port S79O
S80I: J4.15 ; port S80I
S80O: J4.68 ; port S80O
S81I: J4.69 ; port S81I
S81O: J5.5 ; port S81O
S82I: J4.70 ; port S82I
S82O: J5.6 ; port S82O
S83I: J4.71 ; port S83I
S83O: J5.7 ; port S83O
S84I: J4.72 ; port S84I
S84O: J5.8 ; port S84O
S85I: J4.73 ; port S85I
S85O: J5.9 ; port S85O
S86I: J4.74 ; port S86I
S86O: J5.10 ; port S86O
S87I: J4.75 ; port S87I
S87O: J5.11 ; port S87O
S88I: J4.76 ; port S88I
S88O: J5.12 ; port S88O
S89I: J4.77 ; port S89I
S89O: J5.13 ; port S89O
S90I: J4.78 ; port S90I
S90O: J5.51 ; port S90O
S91I: J4.79 ; port S91I
S91O: J5.52 ; port S91O
S92I: J4.80 ; port S92I
S92O: J5.53 ; port S92O
S93I: J5.1 ; port S93I
S93O: J5.54 ; port S93O
S94I: J5.2 ; port S94I
S94O: J5.55 ; port S94O
S95I: J5.3 ; port S95I
S95O: J5.56 ; port S95O
S96I: J5.4 ; port S96I
S96O: J5.57 ; port S96O
S97I: J5.58 ; port S97I
S97O: J5.74 ; port S97O
S98I: J5.59 ; port S98I
S98O: J5.75 ; port S98O
S99I: J5.60 ; port S99I
S99O: J5.76 ; port S99O
S100I: J5.61 ; port S100I
S100O: J5.77 ; port S100O
S101I: J5.62 ; port S101I
S101O: J5.78 ; port S101O
S102I: J5.63 ; port S102I
S102O: J5.79 ; port S102O
S103I: J5.64 ; port S103I
S103O: J5.80 ; port S103O
S104I: J5.65 ; port S104I
S104O: J6.1 ; port S104O
S105I: J5.66 ; port S105I
S105O: J6.2 ; port S105O
S106I: J5.67 ; port S106I
S106O: J6.3 ; port S106O
S107I: J5.68 ; port S107I
S107O: J6.4 ; port S107O
S108I: J5.69 ; port S108I
S108O: J6.5 ; port S108O
S109I: J5.70 ; port S109I
S109O: J6.6 ; port S109O
S110I: J5.71 ; port S110I
S110O: J6.7 ; port S110O
S111I: J5.72 ; port S111I
S111O: J1.38 ; port S111O
S112I: J5.73 ; port S112I
S112O: J1.39 ; port S112O
S113I: J1.40 ; port S113I
S113O: J1.56 ; port S113O
S114I: J1.41 ; port S114I
S114O: J1.57 ; port S114O
S115I: J1.42 ; port S115I
S115O: J1.58 ; port S115O
S116I: J1.43 ; port S116I
S116O: J1.59 ; port S116O
S117I: J1.44 ; port S117I
S117O: J1.60 ; port S117O
S118I: J1.45 ; port S118I
S118O: J1.61 ; port S118O
S119I: J1.46 ; port S119I
S119O: J1.62 ; port S119O
S120I: J1.47 ; port S120I
S120O: J1.63 ; port S120O
S121I: J1.48 ; port S121I
S121O: J1.64 ; port S121O
S122I: J1.49 ; port S122I
S122O: J1.65 ; port S122O
S123I: J1.50 ; port S123I
S123O: J1.66 ; port S123O
S124I: J1.51 ; port S124I
S124O: J1.67 ; port S124O
S125I: J1.52 ; port S125I
S125O: J1.68 ; port S125O
S126I: J1.53 ; port S126I
S126O: J1.69 ; port S126O
S127I: J1.54 ; port S127I
S127O: J1.70 ; port S127O
S128I: J1.55 ; port S128I
S128O: J1.71 ; port S128O
S129I: J1.72 ; port S129I
S129O: J2.45 ; port S129O
S130I: J1.73 ; port S130I
S130O: J2.46 ; port S130O
S131I: J1.74 ; port S131I
S131O: J2.47 ; port S131O
S132I: J2.32 ; port S132I
S132O: J2.48 ; port S132O
S133I: J2.33 ; port S133I
S133O: J2.49 ; port S133O
S134I: J2.34 ; port S134I
S134O: J2.50 ; port S134O
S135I: J2.35 ; port S135I
S135O: J2.51 ; port S135O
S136I: J2.36 ; port S136I
S136O: J2.52 ; port S136O
S137I: J2.37 ; port S137I
S137O: J2.53 ; port S137O
S138I: J2.38 ; port S138I
S138O: J2.54 ; port S138O
S139I: J2.39 ; port S139I
S139O: J2.55 ; port S139O
S140I: J2.40 ; port S140I
S140O: J2.56 ; port S140O
S141I: J2.41 ; port S141I
S141O: J2.57 ; port S141O
S142I: J2.42 ; port S142I
S142O: J2.58 ; port S142O
S143I: J2.43 ; port S143I
S143O: J2.59 ; port S143O
S144I: J2.44 ; port S144I
S144O: J2.60 ; port S144O
S145I: J2.61 ; port S145I
S145O: J3.34 ; port S145O
S146I: J2.62 ; port S146I
S146O: J3.35 ; port S146O
S147I: J2.63 ; port S147I
S147O: J3.36 ; port S147O
S148I: J2.64 ; port S148I
S148O: J3.37 ; port S148O
S149I: J2.65 ; port S149I
S149O: J3.38 ; port S149O
S150I: J2.66 ; port S150I
S150O: J3.39 ; port S150O
S151I: J2.67 ; port S151I
S151O: J3.40 ; port S151O
S152I: J2.68 ; port S152I
S152O: J3.41 ; port S152O
S153I: J3.26 ; port S153I
S153O: J3.42 ; port S153O
S154I: J3.27 ; port S154I
S154O: J3.43 ; port S154O
S155I: J3.28 ; port S155I
S155O: J3.44 ; port S155O
S156I: J3.29 ; port S156I
S156O: J3.45 ; port S156O
S157I: J3.30 ; port S157I
S157O: J3.46 ; port S157O
S158I: J3.31 ; port S158I
S158O: J3.47 ; port S158O
S159I: J3.32 ; port S159I
S159O: J3.48 ; port S159O
S160I: J3.33 ; port S160I
S160O: J3.49 ; port S160O
S161I: J3.50 ; port S161I
S161O: J4.23 ; port S161O
S162I: J3.51 ; port S162I
S162O: J4.24 ; port S162O
S163I: J3.52 ; port S163I
S163O: J4.25 ; port S163O
S164I: J3.53 ; port S164I
S164O: J4.26 ; port S164O
S165I: J3.54 ; port S165I
S165O: J4.27 ; port S165O
S166I: J3.55 ; port S166I
S166O: J4.28 ; port S166O
S167I: J3.56 ; port S167I
S167O: J4.29 ; port S167O
S168I: J3.57 ; port S168I
S168O: J4.30 ; port S168O
S169I: J3.58 ; port S169I
S169O: J4.31 ; port S169O
S170I: J3.59 ; port S170I
S170O: J4.32 ; port S170O
S171I: J3.60 ; port S171I
S171O: J4.33 ; port S171O
S172I: J3.61 ; port S172I
S172O: J4.34 ; port S172O
S173I: J3.62 ; port S173I
S173O: J4.35 ; port S173O
S174I: J4.20 ; port S174I
S174O: J4.36 ; port S174O
S175I: J4.21 ; port S175I
S175O: J4.37 ; port S175O
S176I: J4.22 ; port S176I
S176O: J4.38 ; port S176O
S177I: J4.39 ; port S177I
S177O: J4.55 ; port S177O
S178I: J4.40 ; port S178I
S178O: J4.56 ; port S178O
S179I: J4.41 ; port S179I
S179O: J5.14 ; port S179O
S180I: J4.42 ; port S180I
S180O: J5.15 ; port S180O
S181I: J4.43 ; port S181I
S181O: J5.16 ; port S181O
S182I: J4.44 ; port S182I
S182O: J5.17 ; port S182O
S183I: J4.45 ; port S183I
S183O: J5.18 ; port S183O
S184I: J4.46 ; port S184I
S184O: J5.19 ; port S184O
S185I: J4.47 ; port S185I
S185O: J5.20 ; port S185O
S186I: J4.48 ; port S186I
S186O: J5.21 ; port S186O
S187I: J4.49 ; port S187I
S187O: J5.22 ; port S187O
S188I: J4.50 ; port S188I
S188O: J5.23 ; port S188O
S189I: J4.51 ; port S189I
S189O: J5.24 ; port S189O
S190I: J4.52 ; port S190I
S190O: J5.25 ; port S190O
S191I: J4.53 ; port S191I
S191O: J5.26 ; port S191O
S192I: J4.54 ; port S192I
S192O: J5.27 ; port S192O
S193I: J5.28 ; port S193I
S193O: J5.44 ; port S193O
S194I: J5.29 ; port S194I
S194O: J5.45 ; port S194O
S195I: J5.30 ; port S195I
S195O: J5.46 ; port S195O
S196I: J5.31 ; port S196I
S196O: J5.47 ; port S196O
S197I: J5.32 ; port S197I
S197O: J5.48 ; port S197O
S198I: J5.33 ; port S198I
S198O: J5.49 ; port S198O
S199I: J5.34 ; port S199I
S199O: J5.50 ; port S199O
S200I: J5.35 ; port S200I
S200O: J6.8 ; port S200O
S201I: J5.36 ; port S201I
S201O: J6.9 ; port S201O
S202I: J5.37 ; port S202I
S202O: J6.10 ; port S202O
S203I: J5.38 ; port S203I
S203O: J6.11 ; port S203O
S204I: J5.39 ; port S204I
S204O: J6.12 ; port S204O
S205I: J5.40 ; port S205I
S205O: J6.13 ; port S205O
S206I: J5.41 ; port S206I
S206O: J6.14 ; port S206O
S207I: J5.42 ; port S207I
S207O: J6.15 ; port S207O
S208I: J5.43 ; port S208I
S208O: J6.16 ; port S208O
S209I: J6.17 ; port S209I
S209O: J6.33 ; port S209O
S210I: J6.18 ; port S210I
S210O: J6.34 ; port S210O
S211I: J6.19 ; port S211I
S211O: J6.35 ; port S211O
S212I: J6.20 ; port S212I
S212O: J6.36 ; port S212O
S213I: J6.21 ; port S213I
S213O: J6.37 ; port S213O
S214I: J6.22 ; port S214I
S214O: J6.38 ; port S214O
S215I: J6.23 ; port S215I
S215O: J6.39 ; port S215O
S216I: J6.24 ; port S216I
S216O: J6.40 ; port S216O
S217I: J6.25 ; port S217I
S217O: J6.41 ; port S217O
S218I: J6.26 ; port S218I
S218O: J6.42 ; port S218O
S219I: J6.27 ; port S219I
S219O: J6.43 ; port S219O
S220I: J6.28 ; port S220I
S220O: J6.44 ; port S220O
S221I: J6.29 ; port S221I
S221O: J6.45 ; port S221O
S222I: J6.30 ; port S222I
S222O: J6.46 ; port S222O
S223I: J6.31 ; port S223I
S223O: J6.47 ; port S223O
S224I: J6.32 ; port S224I
S224O: J6.48 ; port S224O

Not connected (* = marked no-connect by the designer): J6 49 50 51 52 53 54 55 56 57 58 59 60 61 62 63 64 65 66 67 68 69 70 71 72 73 74 75 76 77 78 79 80

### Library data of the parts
J1-J6 = 2X40 HDR: HEADER, 80 PIN; NAME: 80 PIN HEADER

## Sheet Controller.SchDoc: P.C. BOARD
size A2; Revision: A; SheetNumber: 2; SheetTotal: 19
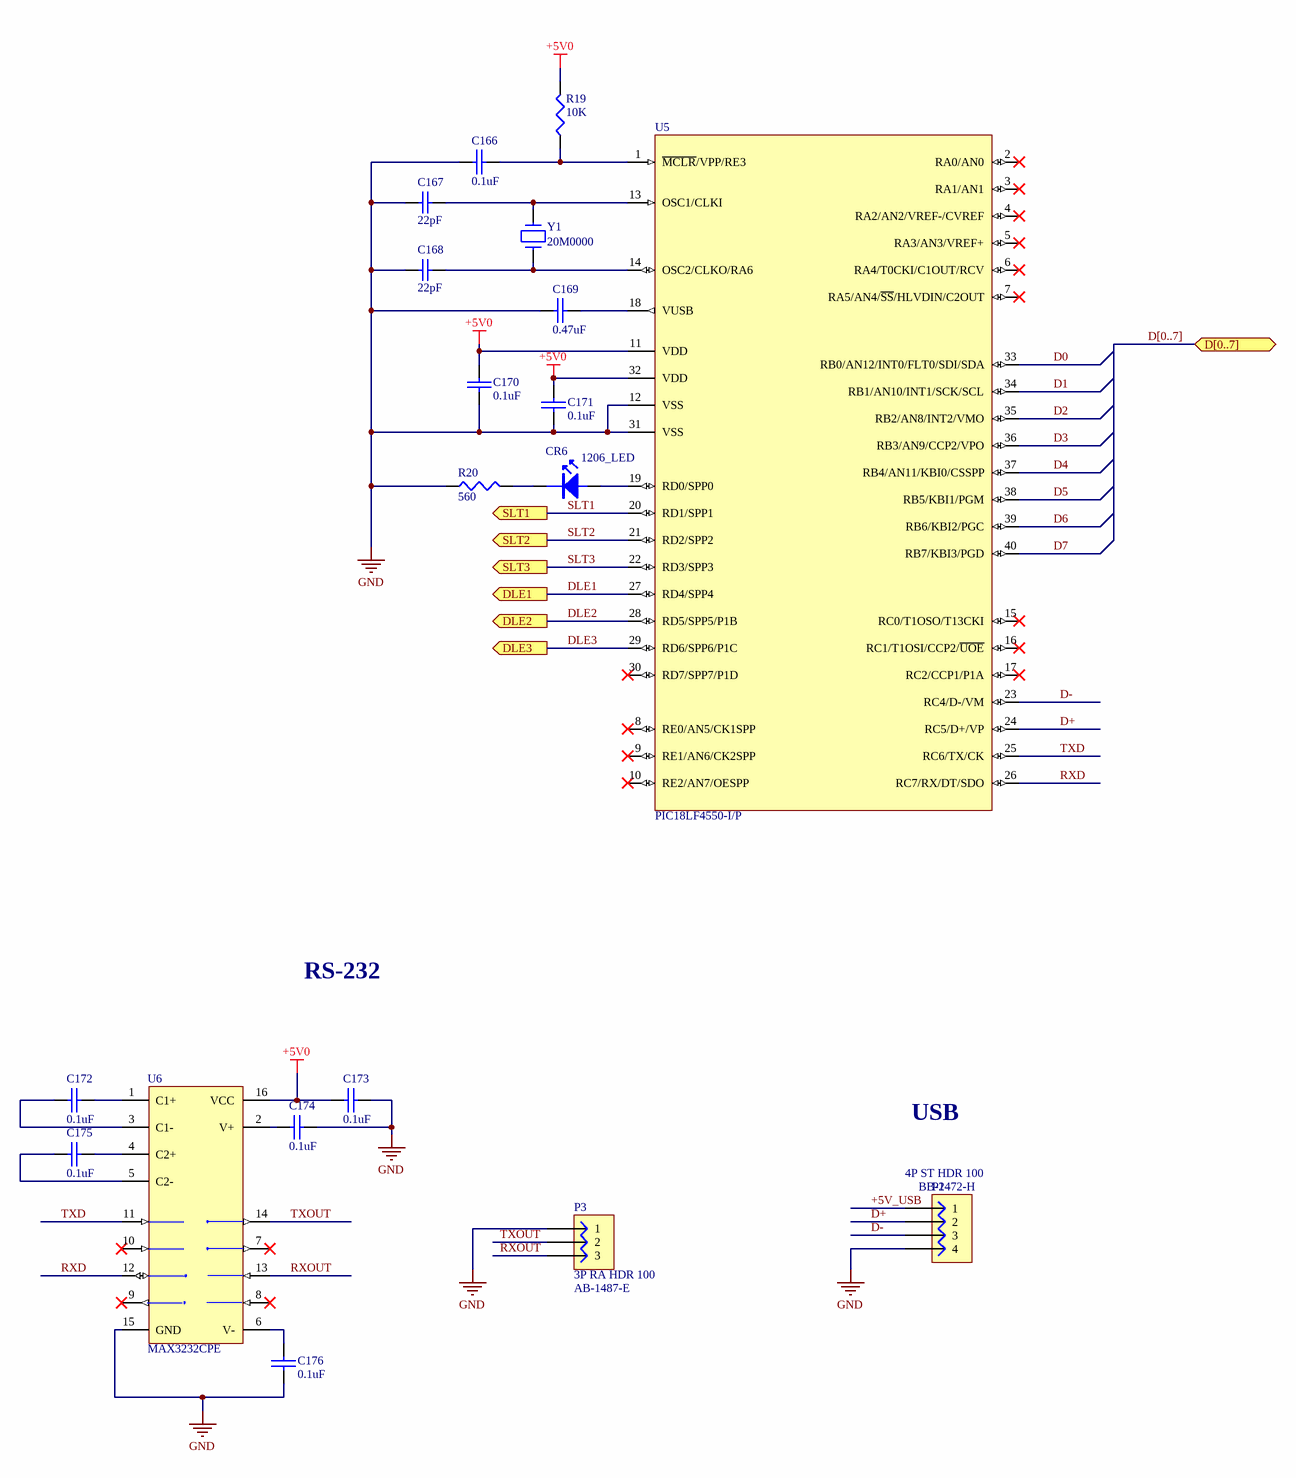
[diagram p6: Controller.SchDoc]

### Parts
C166  value 0.1uF  [0805/1.3/N]  (hidden comment: 104-50V-10CX0805)
C167  value 22pF  [0402/0.6/N]  (hidden comment: 22P-25V-10NX0402)
C168  value 22pF  [0402/0.6/N]  (hidden comment: 22P-25V-10NX0402)
C169  value 0.47uF  [0805/1.4/N]  (hidden comment: 474-50V-10CX0805)
C170  value 0.1uF  [0805/1.3/N]  (hidden comment: 104-50V-10CX0805)
C171  value 0.1uF  [0805/1.3/N]  (hidden comment: 104-50V-10CX0805)
C172  value 0.1uF  [0805/1.3/N]  (hidden comment: 104-50V-10CX0805)
C173  value 0.1uF  [0805/1.3/N]  (hidden comment: 104-50V-10CX0805)
C174  value 0.1uF  [0805/1.3/N]  (hidden comment: 104-50V-10CX0805)
C175  value 0.1uF  [0805/1.3/N]  (hidden comment: 104-50V-10CX0805)
C176  value 0.1uF  [0805/1.3/N]  (hidden comment: 104-50V-10CX0805)
CR6  1206_LED  [1206D/K/NP]
P2  AMETEK PART NO: BB-1472-H  [SIP4]  (hidden comment: 4P ST HDR 100)
P3  AMETEK PART NO: AB-1487-E  [H3RA100]  (hidden comment: 3P RA HDR 100)
R19  value 10K  [0805/N]  (hidden comment: R10K00D1#0AX0805)
R20  value 560  [AX.55/.125L]  (hidden comment: R56R00E1#0EW)
U5  PIC18LF4550-I/P  [DIP40]
U6  MAX3232CPE  [DIP-18]
Y1  20M0000  [XTAL3_I]

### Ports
D[0..7] (bidir), DLE1 (out), DLE2 (out), DLE3 (out), SLT1 (out), SLT2 (out), SLT3 (out)

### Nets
+5V0: C170.2 C171.2 C173.2 R19.2 U5.11(VDD) U5.32(VDD) U6.16(VCC)
GND: C166.1 C167.1 C168.1 C169.1 C170.1 C171.1 C173.1 C174.1 C176.1 P2.4 P3.1 R20.1 U5.12(VSS) U5.31(VSS) U6.15(GND)
+5V_USB: P2.1
D0: U5.33(RB0/AN12/INT0/FLT0/SDI/SDA)
D1: U5.34(RB1/AN10/INT1/SCK/SCL)
D2: U5.35(RB2/AN8/INT2/VMO)
D3: U5.36(RB3/AN9/CCP2/VPO)
D4: U5.37(RB4/AN11/KBI0/CSSPP)
D5: U5.38(RB5/KBI1/PGM)
D6: U5.39(RB6/KBI2/PGC)
D7: U5.40(RB7/KBI3/PGD)
D+: P2.2 U5.24(RC5/D+/VP)
D-: P2.3 U5.23(RC4/D-/VM)
DLE1: U5.27(RD4/SPP4) ; port DLE1
DLE2: U5.28(RD5/SPP5/P1B) ; port DLE2
DLE3: U5.29(RD6/SPP6/P1C) ; port DLE3
RXD: U5.26(RC7/RX/DT/SDO) U6.12(R1OUT)
RXOUT: P3.3 U6.13(R1IN)
SLT1: U5.20(RD1/SPP1) ; port SLT1
SLT2: U5.21(RD2/SPP2) ; port SLT2
SLT3: U5.22(RD3/SPP3) ; port SLT3
TXD: U5.25(RC6/TX/CK) U6.11(T1IN)
TXOUT: P3.2 U6.14(T1OUT)
NetC166_2: C166.2 R19.1 U5.1(~{MCLR}/VPP/RE3)
NetC167_2: C167.2 U5.13(OSC1/CLKI) Y1.2
NetC168_2: C168.2 U5.14(OSC2/CLKO/RA6) Y1.1
NetC169_2: C169.2 U5.18(VUSB)
NetC172_1: C172.1 U6.3(C1-)
NetC172_2: C172.2 U6.1(C1+)
NetC174_2: C174.2 U6.2(V+)
NetC175_1: C175.1 U6.5(C2-)
NetC175_2: C175.2 U6.4(C2+)
NetC176_2: C176.2 U6.6(V-)
NetCR6_1: CR6.1(K) R20.2
NetCR6_2: CR6.2(A) U5.19(RD0/SPP0)

Not connected (* = marked no-connect by the designer): U5 2(RA0/AN0)* 3(RA1/AN1)* 4(RA2/AN2/VREF-/CVREF)* 5(RA3/AN3/VREF+)* 6(RA4/T0CKI/C1OUT/RCV)* 7(RA5/AN4/~{SS}/HLVDIN/C2OUT)* 8(RE0/AN5/CK1SPP)* 9(RE1/AN6/CK2SPP)* 10(RE2/AN7/OESPP)* 15(RC0/T1OSO/T13CKI)* 16(RC1/T1OSI/CCP2/~{UOE})* 17(RC2/CCP1/P1A)* 30(RD7/SPP7/P1D)*; U6 7(T2OUT)* 8(R2IN)* 9(R2OUT)* 10(T2IN)*

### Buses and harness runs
bus D[0..7] = port D[0..7]

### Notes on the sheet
- RS-232
- USB

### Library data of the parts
C166 C170-C176 = 104-50V-10CX0805: as C41 on sheet ByPass
C167 C168 = 22P-25V-10NX0402: CAP CERAMIC 22PF 25V 10% COG 0402; AMETEK PART NO: B1605-082; AREA: 0.0017; CHECKER: RSK 8/7/13; DESIGNER: GTN  10/31/11
C169 = 474-50V-10CX0805: CAPACITOR, CERAMIC, 0.47UF 10%, X7R, 50V, 0805; AMETEK PART NO: B1605-063; AREA: 0.0066; TOLERANCE: 10; TYPE: CAP_X; CHECKER: CC 4/23/13; DESIGNER: GWL 8/5/05
CR6 = 1206_LED_GRN: LED, GRN, SMT; AMETEK PART NO: O516-P-002; AREA: 0.0116; TYPE: LED_X; DESIGNER: GTN 4/25/02   GRL 5/2/02
P2 = 4P ST HDR 100: HEADER, 4 PIN, ST, 0.100 CTRS
P3 = 3P RA HDR 100: HEADER, 3 PIN, RA, 0.100 CTRS; AREA: 0.15; DESIGNER: GTN 3/20/08
R19 = R10K00D1#0AX0805: as R3 on sheet 15 and 5 Volts
R20 = R56R00E1#0EW: RESISTOR, 56 OHMS, 1%, 20PPM, SILICONE-CERAMIC WIREWOUND; AMETEK PART NO: B1604-H-002; AREA: 0.11; DESIGNER: GRL 8/17/05
U5 = PIC18LF4550-I/P: High Performance, Enhanced Flash, USB Microcontroller with nanoWatt Technology, 32K Flash, 40-Pin PDIP, Industrial Temperature Range
U6 = MAX3232CPE: 3.0V TO 5.5V, Low-Power, up to 1Mbps, True RS-232 Transceiver Using Four 0.1µF External Capacitor
Y1 = 12M0000: 12.0000 MHZ XTAL; AMETEK PART NO: CB-1535-S

## Sheet Decoder.SchDoc: P.C. BOARD
size A2; Revision: A; SheetNumber: 0; SheetTotal: 0
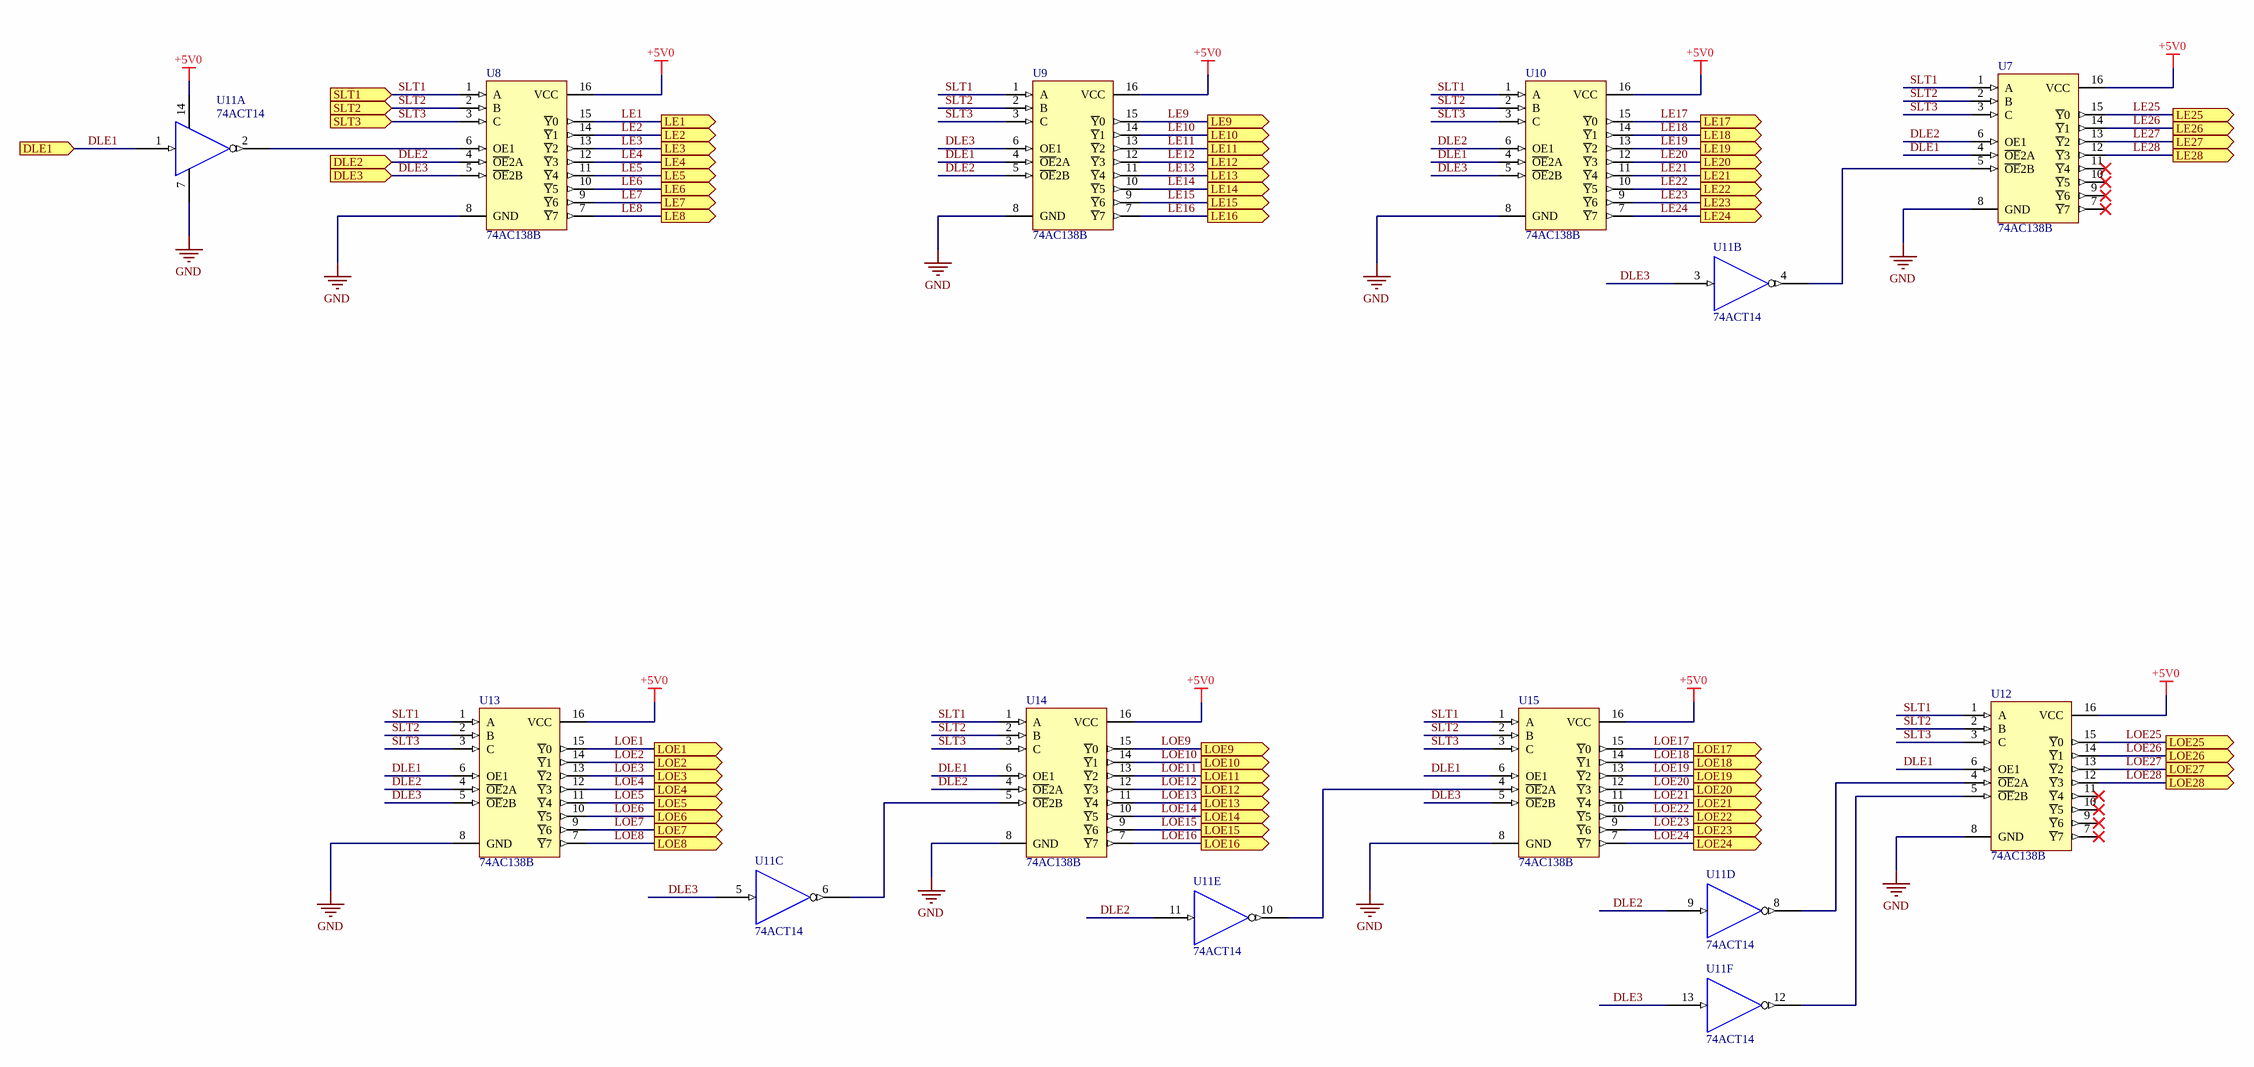
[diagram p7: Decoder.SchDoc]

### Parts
U7  74AC138B  [DIP16]
U8  74AC138B  [DIP16]
U9  74AC138B  [DIP16]
U10  74AC138B  [DIP16]
U11  74ACT14  [DIP14]  (parts A,B,C,D,E,F of 6)
U12  74AC138B  [DIP16]
U13  74AC138B  [DIP16]
U14  74AC138B  [DIP16]
U15  74AC138B  [DIP16]

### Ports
DLE1 (in), DLE2 (in), DLE3 (in), LE1 (out), LE2 (out), LE3 (out), LE4 (out), LE5 (out), LE6 (out), LE7 (out), LE8 (out), LE9 (out), LE10 (out), LE11 (out), LE12 (out), LE13 (out), LE14 (out), LE15 (out), LE16 (out), LE17 (out), LE18 (out), LE19 (out), LE20 (out), LE21 (out), LE22 (out), LE23 (out), LE24 (out), LE25 (out), LE26 (out), LE27 (out), LE28 (out), LOE1 (out), LOE2 (out), LOE3 (out), LOE4 (out), LOE5 (out), LOE6 (out), LOE7 (out), LOE8 (out), LOE9 (out), LOE10 (out), LOE11 (out), LOE12 (out), LOE13 (out), LOE14 (out), LOE15 (out), LOE16 (out), LOE17 (out), LOE18 (out), LOE19 (out), LOE20 (out), LOE21 (out), LOE22 (out), LOE23 (out), LOE24 (out), LOE25 (out), LOE26 (out), LOE27 (out), LOE28 (out), SLT1 (in), SLT2 (in), SLT3 (in)

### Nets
+5V0: U7.16(VCC) U8.16(VCC) U9.16(VCC) U10.16(VCC) U11.14 U12.16(VCC) U13.16(VCC) U14.16(VCC) U15.16(VCC)
GND: U7.8(GND) U8.8(GND) U9.8(GND) U10.8(GND) U11.7 U12.8(GND) U13.8(GND) U14.8(GND) U15.8(GND)
DLE1: U7.4(~{OE}2A) U9.4(~{OE}2A) U10.4(~{OE}2A) U11.1 U12.6(OE1) U13.6(OE1) U14.6(OE1) U15.6(OE1) ; port DLE1
DLE2: U7.6(OE1) U8.4(~{OE}2A) U9.5(~{OE}2B) U10.6(OE1) U11.9 U11.11 U13.4(~{OE}2A) U14.4(~{OE}2A) ; port DLE2
DLE3: U8.5(~{OE}2B) U9.6(OE1) U10.5(~{OE}2B) U11.3 U11.5 U11.13 U13.5(~{OE}2B) U15.5(~{OE}2B) ; port DLE3
LE1: U8.15(~{Y}0) ; port LE1
LE2: U8.14(~{Y}1) ; port LE2
LE3: U8.13(~{Y}2) ; port LE3
LE4: U8.12(~{Y}3) ; port LE4
LE5: U8.11(~{Y}4) ; port LE5
LE6: U8.10(~{Y}5) ; port LE6
LE7: U8.9(~{Y}6) ; port LE7
LE8: U8.7(~{Y}7) ; port LE8
LE9: U9.15(~{Y}0) ; port LE9
LE10: U9.14(~{Y}1) ; port LE10
LE11: U9.13(~{Y}2) ; port LE11
LE12: U9.12(~{Y}3) ; port LE12
LE13: U9.11(~{Y}4) ; port LE13
LE14: U9.10(~{Y}5) ; port LE14
LE15: U9.9(~{Y}6) ; port LE15
LE16: U9.7(~{Y}7) ; port LE16
LE17: U10.15(~{Y}0) ; port LE17
LE18: U10.14(~{Y}1) ; port LE18
LE19: U10.13(~{Y}2) ; port LE19
LE20: U10.12(~{Y}3) ; port LE20
LE21: U10.11(~{Y}4) ; port LE21
LE22: U10.10(~{Y}5) ; port LE22
LE23: U10.9(~{Y}6) ; port LE23
LE24: U10.7(~{Y}7) ; port LE24
LE25: U7.15(~{Y}0) ; port LE25
LE26: U7.14(~{Y}1) ; port LE26
LE27: U7.13(~{Y}2) ; port LE27
LE28: U7.12(~{Y}3) ; port LE28
LOE1: U13.15(~{Y}0) ; port LOE1
LOE2: U13.14(~{Y}1) ; port LOE2
LOE3: U13.13(~{Y}2) ; port LOE3
LOE4: U13.12(~{Y}3) ; port LOE4
LOE5: U13.11(~{Y}4) ; port LOE5
LOE6: U13.10(~{Y}5) ; port LOE6
LOE7: U13.9(~{Y}6) ; port LOE7
LOE8: U13.7(~{Y}7) ; port LOE8
LOE9: U14.15(~{Y}0) ; port LOE9
LOE10: U14.14(~{Y}1) ; port LOE10
LOE11: U14.13(~{Y}2) ; port LOE11
LOE12: U14.12(~{Y}3) ; port LOE12
LOE13: U14.11(~{Y}4) ; port LOE13
LOE14: U14.10(~{Y}5) ; port LOE14
LOE15: U14.9(~{Y}6) ; port LOE15
LOE16: U14.7(~{Y}7) ; port LOE16
LOE17: U15.15(~{Y}0) ; port LOE17
LOE18: U15.14(~{Y}1) ; port LOE18
LOE19: U15.13(~{Y}2) ; port LOE19
LOE20: U15.12(~{Y}3) ; port LOE20
LOE21: U15.11(~{Y}4) ; port LOE21
LOE22: U15.10(~{Y}5) ; port LOE22
LOE23: U15.9(~{Y}6) ; port LOE23
LOE24: U15.7(~{Y}7) ; port LOE24
LOE25: U12.15(~{Y}0) ; port LOE25
LOE26: U12.14(~{Y}1) ; port LOE26
LOE27: U12.13(~{Y}2) ; port LOE27
LOE28: U12.12(~{Y}3) ; port LOE28
SLT1: U7.1(A) U8.1(A) U9.1(A) U10.1(A) U12.1(A) U13.1(A) U14.1(A) U15.1(A) ; port SLT1
SLT2: U7.2(B) U8.2(B) U9.2(B) U10.2(B) U12.2(B) U13.2(B) U14.2(B) U15.2(B) ; port SLT2
SLT3: U7.3(C) U8.3(C) U9.3(C) U10.3(C) U12.3(C) U13.3(C) U14.3(C) U15.3(C) ; port SLT3
NetU7_5: U7.5(~{OE}2B) U11.4
NetU8_6: U8.6(OE1) U11.2
NetU11_6: U11.6 U14.5(~{OE}2B)
NetU11_8: U11.8 U12.4(~{OE}2A)
NetU11_10: U11.10 U15.4(~{OE}2A)
NetU11_12: U11.12 U12.5(~{OE}2B)

Not connected (* = marked no-connect by the designer): U7 7(~{Y}7)* 9(~{Y}6)* 10(~{Y}5)* 11(~{Y}4)*; U12 7(~{Y}7)* 9(~{Y}6)* 10(~{Y}5)* 11(~{Y}4)*

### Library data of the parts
U7-U10 U12-U15 = 74AC138B: 3-to-8 Line Decoder Inverting
U11 = 74ACT14: IC, CMOS HEX INVERTER , DIP14; AMETEK PART NO: AB-1503-G; AREA: .263; DESIGNER: LEGACY PART 2/9/04 GTN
